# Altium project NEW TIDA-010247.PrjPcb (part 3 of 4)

## Sheet High side FETs.SchDoc
size A2; SheetNumber: 5; SheetTotal: 10
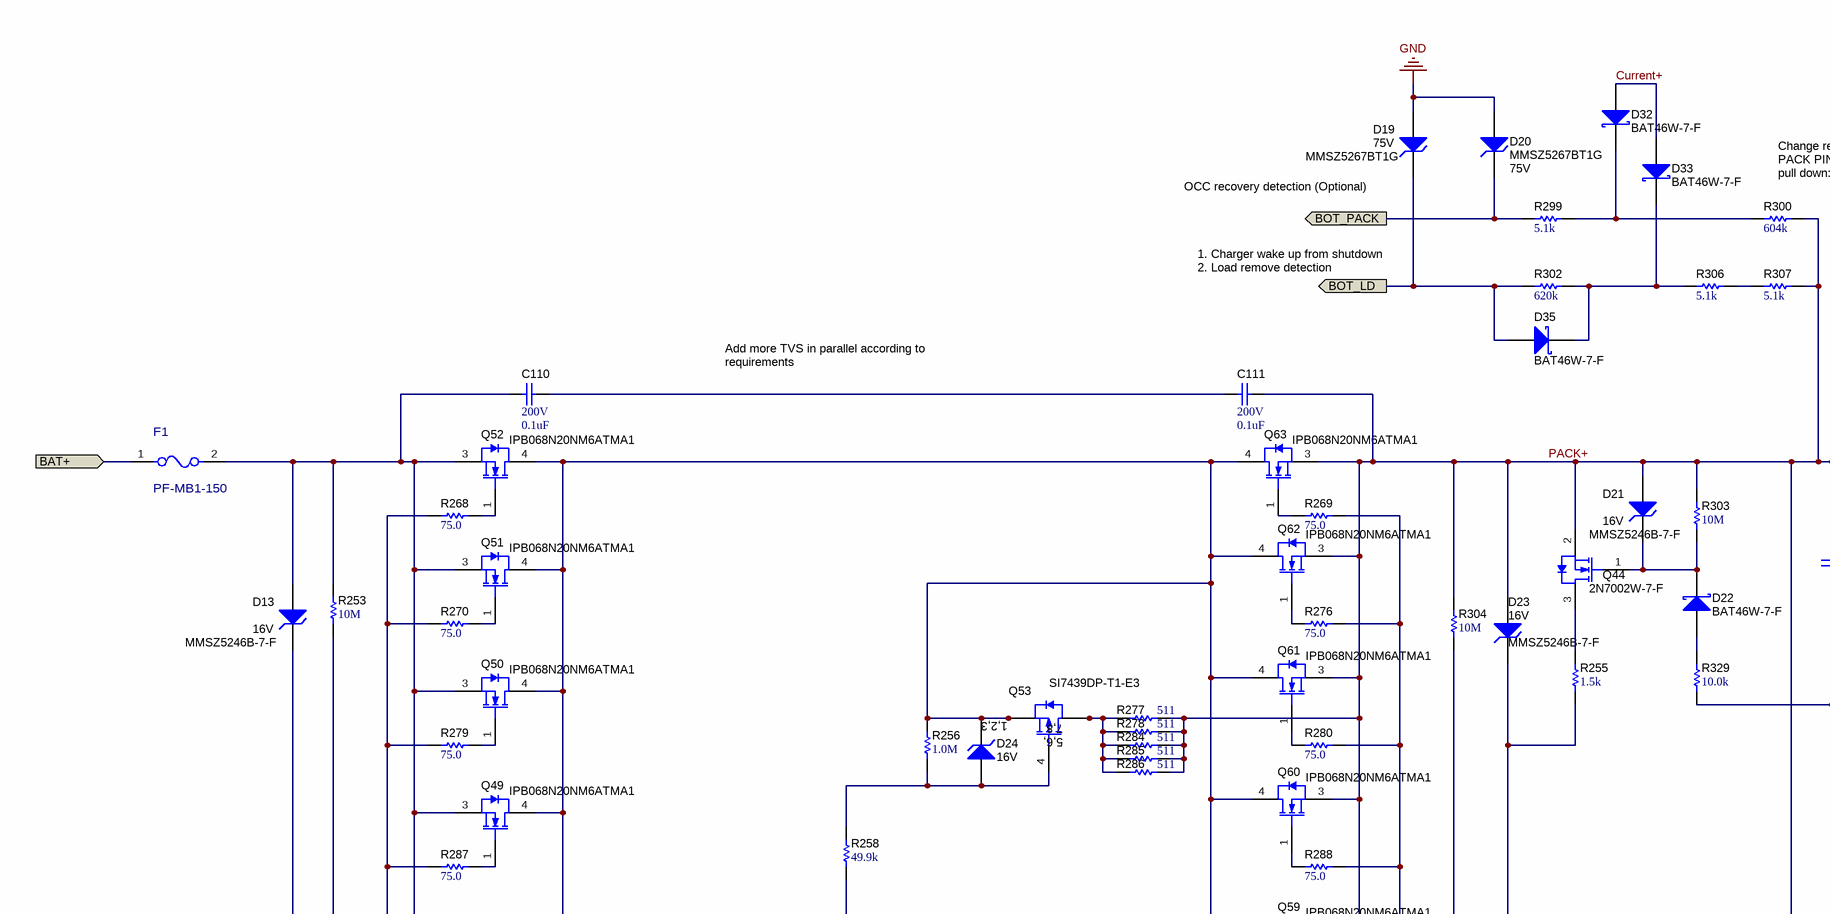
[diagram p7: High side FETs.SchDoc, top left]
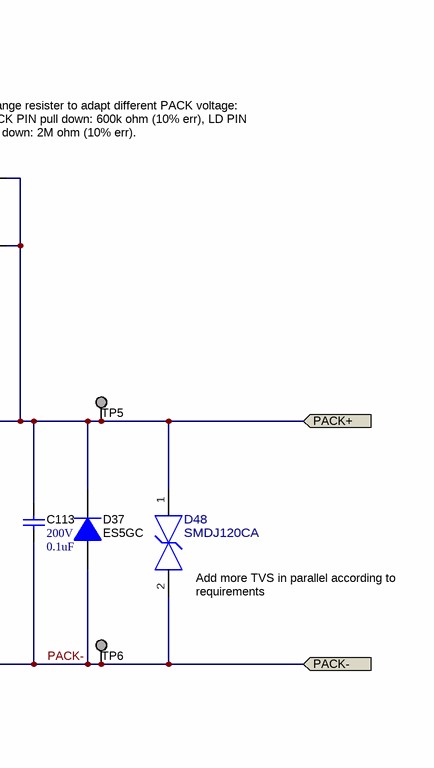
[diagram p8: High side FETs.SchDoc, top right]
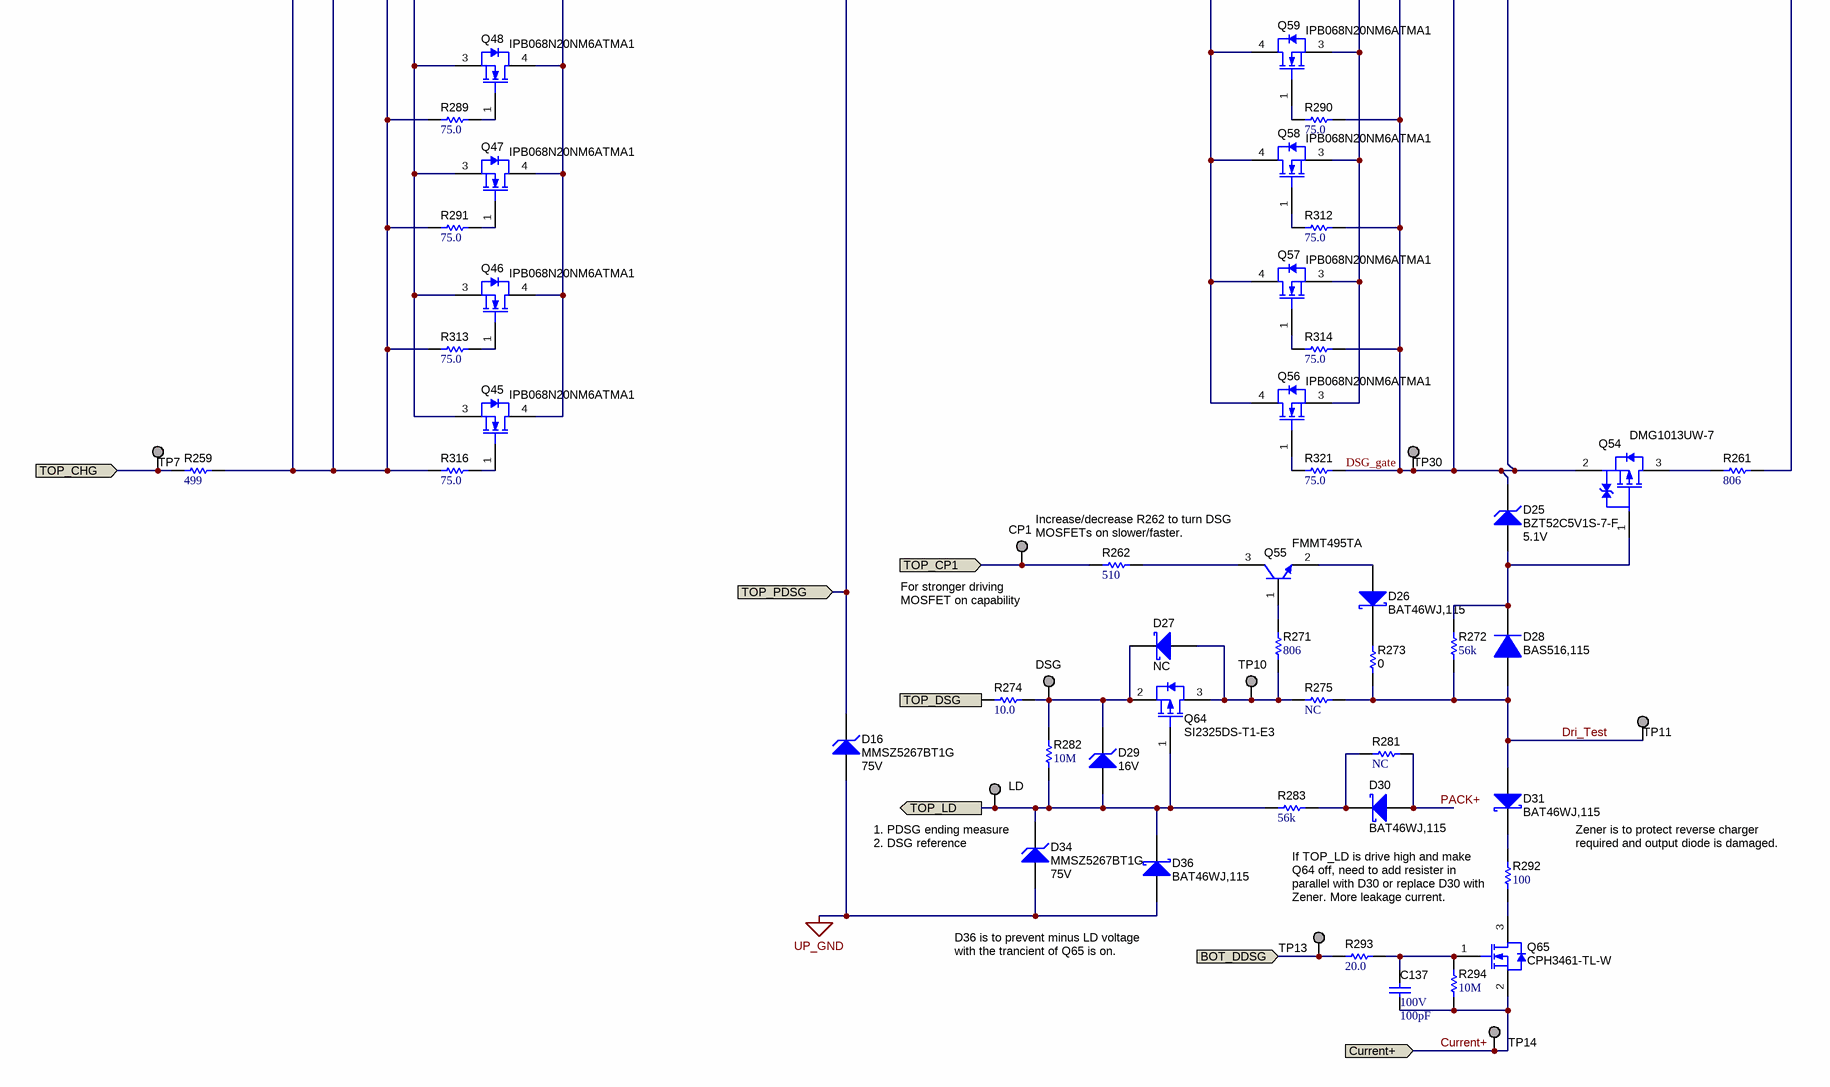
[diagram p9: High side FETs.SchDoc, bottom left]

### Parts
C110  VDC_V: 200V  ValueDisplayed: 0.1uF  [1206]  (hidden comment: C1206C104K2RACTU)
C111  VDC_V: 200V  ValueDisplayed: 0.1uF  [1206]  (hidden comment: C1206C104K2RACTU)
C113  VDC_V: 200V  ValueDisplayed: 0.1uF  [1206]  (hidden comment: C1206C104K2RACTU)
C137  VDC_V: 100V  ValueDisplayed: 100pF  [0603]  (hidden comment: GRM1885C2A101JA01D)  (no BOM)
CP1    [TP_SM_1MM]  (value not drawn)  (no BOM)
D13  MMSZ5246B-7-F  value 16V  [SOD-123]
D16  MMSZ5267BT1G  value 75V  [SOD-123]
D19  MMSZ5267BT1G  value 75V  [SOD-123]
D20  MMSZ5267BT1G  value 75V  [SOD-123]
D21  MMSZ5246B-7-F  value 16V  [SOD-123]
D22  BAT46W-7-F  [SOD-123]
D23  MMSZ5246B-7-F  value 16V  [SOD-123]
D24  value 16V  [SOD-123]  (hidden comment: MMSZ5246B-7-F)
D25  BZT52C5V1S-7-F  value 5.1V  [SOD-323]
D26  BAT46WJ,115  [SOD-323F]
D27  NC  [SOD-323F]  (no BOM)
D28  BAS516,115  [SOD-523]
D29  value 16V  [SOD-123]  (hidden comment: MMSZ5246B-7-F)
D30  BAT46WJ,115  [SOD-323F]
D31  BAT46WJ,115  [SOD-323F]
D32  BAT46W-7-F  [SOD-123]
D33  BAT46W-7-F  [SOD-123]
D34  MMSZ5267BT1G  value 75V  [SOD-123]
D35  BAT46W-7-F  [SOD-123]
D36  BAT46WJ,115  [SOD-323F]
D37  ES5GC  [SMC]
D48  SMDJ120CA  [FP-SMDJ54CA_DO-214AB-MFG]
DSG    [TP_SM_1MM]  (value not drawn)  (no BOM)
F1  PF-MB1-150  [FP-PF-MB1-150_BT_FUSE_56MM0_17MM4-MFG]
LD    [TP_SM_1MM]  (value not drawn)  (no BOM)
Q44  2N7002W-7-F  [SOT-323]
Q45  IPB068N20NM6ATMA1  [DDPAK]
Q46  IPB068N20NM6ATMA1  [DDPAK]
Q47  IPB068N20NM6ATMA1  [DDPAK]
Q48  IPB068N20NM6ATMA1  [DDPAK]
Q49  IPB068N20NM6ATMA1  [DDPAK]
Q50  IPB068N20NM6ATMA1  [DDPAK]
Q51  IPB068N20NM6ATMA1  [DDPAK]
Q52  IPB068N20NM6ATMA1  [DDPAK]
Q53  SI7439DP-T1-E3  [PowerPAK_SO-8]
Q54  DMG1013UW-7  [SOT-323]
Q55  FMMT495TA  [SOT-23]
Q56  IPB068N20NM6ATMA1  [DDPAK]
Q57  IPB068N20NM6ATMA1  [DDPAK]
Q58  IPB068N20NM6ATMA1  [DDPAK]
Q59  IPB068N20NM6ATMA1  [DDPAK]
Q60  IPB068N20NM6ATMA1  [DDPAK]
Q61  IPB068N20NM6ATMA1  [DDPAK]
Q62  IPB068N20NM6ATMA1  [DDPAK]
Q63  IPB068N20NM6ATMA1  [DDPAK]
Q64  SI2325DS-T1-E3  [SOT-23]
Q65  CPH3461-TL-W  [SOT-23]
R253  ValueDisplayed: 10M  [0603]  (hidden comment: CRCW060310M0JNEA)
R255  ValueDisplayed: 1.5k  [0805_HV]  (hidden comment: CRCW08051K50JNEA)
R256  ValueDisplayed: 1.0M  [0603]  (hidden comment: CRCW06031M00JNEA)
R258  ValueDisplayed: 49.9k  [0603]  (hidden comment: RT0603BRD0749K9L)
R259  ValueDisplayed: 499  [0603]  (hidden comment: RC0603FR-07499RL)
R261  ValueDisplayed: 806  [0603]  (hidden comment: CRCW0603806RFKEA)
R262  ValueDisplayed: 510  [0603]  (hidden comment: RC0603FR-07510RL)
R268  ValueDisplayed: 75.0  [0603]  (hidden comment: CRCW060375R0FKEA)
R269  ValueDisplayed: 75.0  [0603]  (hidden comment: CRCW060375R0FKEA)
R270  ValueDisplayed: 75.0  [0603]  (hidden comment: CRCW060375R0FKEA)
R271  ValueDisplayed: 806  [0603]  (hidden comment: CRCW0603806RFKEA)
R272  ValueDisplayed: 56k  [0805_HV]  (hidden comment: CRCW080556K0JNEA)
R273  ValueDisplayed: 0  [0603]  (hidden comment: CRCW04020000Z0ED)
R274  ValueDisplayed: 10.0  [0805_HV]  (hidden comment: CRCW080510R0FKEA)
R275  ValueDisplayed: NC  [0603]  (hidden comment: CRCW0603806RFKEA)  (no BOM)
R276  ValueDisplayed: 75.0  [0603]  (hidden comment: CRCW060375R0FKEA)
R277  ValueDisplayed: 511  [1206]  (hidden comment: CRCW1206511RFKEA)
R278  ValueDisplayed: 511  [1206]  (hidden comment: CRCW1206511RFKEA)
R279  ValueDisplayed: 75.0  [0603]  (hidden comment: CRCW060375R0FKEA)
R280  ValueDisplayed: 75.0  [0603]  (hidden comment: CRCW060375R0FKEA)
R281  ValueDisplayed: NC  [0603]  (hidden comment: CRCW060310M0JNEA)  (no BOM)
R282  ValueDisplayed: 10M  [0603]  (hidden comment: CRCW060310M0JNEA)
R283  ValueDisplayed: 56k  [0805_HV]  (hidden comment: CRCW080556K0JNEA)
R284  ValueDisplayed: 511  [1206]  (hidden comment: CRCW1206511RFKEA)
R285  ValueDisplayed: 511  [1206]  (hidden comment: CRCW1206511RFKEA)
R286  ValueDisplayed: 511  [1206]  (hidden comment: CRCW1206511RFKEA)
R287  ValueDisplayed: 75.0  [0603]  (hidden comment: CRCW060375R0FKEA)
R288  ValueDisplayed: 75.0  [0603]  (hidden comment: CRCW060375R0FKEA)
R289  ValueDisplayed: 75.0  [0603]  (hidden comment: CRCW060375R0FKEA)
R290  ValueDisplayed: 75.0  [0603]  (hidden comment: CRCW060375R0FKEA)
R291  ValueDisplayed: 75.0  [0603]  (hidden comment: CRCW060375R0FKEA)
R292  ValueDisplayed: 100  [0603]  (hidden comment: CRCW0603100RFKEA)
R293  ValueDisplayed: 20.0  [0603]  (hidden comment: RC0603FR-0720RL)
R294  ValueDisplayed: 10M  [0603]  (hidden comment: CRCW060310M0JNEA)
R299  ValueDisplayed: 5.1k  [0603]  (hidden comment: CRCW06035K10JNEA)
R300  ValueDisplayed: 604k  [0603]  (hidden comment: RC0603FR-07604KL)
R302  ValueDisplayed: 620k  [0603]  (hidden comment: RC0603FR-07620KL)
R303  ValueDisplayed: 10M  [0603]  (hidden comment: CRCW060310M0JNEA)
R304  ValueDisplayed: 10M  [0603]  (hidden comment: CRCW060310M0JNEA)
R306  ValueDisplayed: 5.1k  [0603]  (hidden comment: CRCW06035K10JNEA)
R307  ValueDisplayed: 5.1k  [0603]  (hidden comment: CRCW06035K10JNEA)
R312  ValueDisplayed: 75.0  [0603]  (hidden comment: CRCW060375R0FKEA)
R313  ValueDisplayed: 75.0  [0603]  (hidden comment: CRCW060375R0FKEA)
R314  ValueDisplayed: 75.0  [0603]  (hidden comment: CRCW060375R0FKEA)
R316  ValueDisplayed: 75.0  [0603]  (hidden comment: CRCW060375R0FKEA)
R321  ValueDisplayed: 75.0  [0603]  (hidden comment: CRCW060375R0FKEA)
R329  ValueDisplayed: 10.0k  [0603]  (hidden comment: CRCW060310K0FKEA)
TP5    [TP_SM_1MM]  (value not drawn)  (no BOM)
TP6    [TP_SM_1MM]  (value not drawn)  (no BOM)
TP7    [TP_SM_1MM]  (value not drawn)  (no BOM)
TP10    [TP_SM_1MM]  (value not drawn)  (no BOM)
TP11    [TP_SM_1MM]  (value not drawn)  (no BOM)
TP13    [TP_SM_1MM]  (value not drawn)  (no BOM)
TP14    [TP_SM_1MM]  (value not drawn)  (no BOM)
TP30  DSG_GATE  [TP_SM_1MM]  (value not drawn)  (no BOM)

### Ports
BAT+ (in), BOT_DDSG (in), BOT_LD (out), BOT_PACK (out), Current+ (in), PACK+ (in), PACK- (in), TOP_CHG (in), TOP_CP1 (in), TOP_DSG (in), TOP_LD (out), TOP_PDSG (in)

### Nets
GND: D19.2(A) D20.2(A)
UP_GND: D16.2(A) D34.2(A) D36.2(A)
BAT+: F1.1 ; port BAT+
BOT_DDSG: R293.1 TP13.1 ; port BOT_DDSG
BOT_LD: D19.1(K) D35.2(A) R302.1 ; port BOT_LD
BOT_PACK: D20.1(K) R299.1 ; port BOT_PACK
Current+: C137.2 D32.2(A) D33.2(A) Q65.2(S) R294.1 TP14.1 ; port Current+
Dri_Test: D28.2(A) D31.2(A) R272.1 R273.1 R275.1 TP11.1
DSG_gate: D23.1(K) D25.1(K) Q54.2(S) R255.1 R269.2 R276.2 R280.2 R288.2 R290.2 R304.1 R312.2 R314.2 R321.2 TP30.1
PACK+: C111.1 C113.1 D21.2(A) D23.2(A) D30.2(A) D37.1(K) D48.1 Q44.2(S) Q56.3(S) Q57.3(S) Q58.3(S) Q59.3(S) Q60.3(S) Q61.3(S) Q62.3(S) Q63.3(S) R261.1 R277.2 R278.2 R281.1 R284.2 R285.2 R286.2 R300.2 R303.2 R304.2 R307.2 TP5.1 ; port PACK+
PACK-: C113.2 D37.2(A) D48.2 R329.1 TP6.1 ; port PACK-
TOP_CHG: R259.1 TP7.1 ; port TOP_CHG
TOP_CP1: CP1.1 R262.1 ; port TOP_CP1
TOP_DSG: R274.1 ; port TOP_DSG
TOP_LD: D29.2(A) D34.1(K) D36.1(K) LD.1 Q64.1(G) R282.1 R283.2 ; port TOP_LD
TOP_PDSG: D16.1(K) R258.1 ; port TOP_PDSG
NetC110_1: C110.1 C111.2
NetC110_2: C110.2 D13.2(A) F1.2 Q45.3(S) Q46.3(S) Q47.3(S) Q48.3(S) Q49.3(S) Q50.3(S) Q51.3(S) Q52.3(S) R253.2
NetC137_1: C137.1 Q65.1(G) R293.2 R294.2
NetD13_1: D13.1(K) R253.1 R259.2 R268.1 R270.1 R279.1 R287.1 R289.1 R291.1 R313.1 R316.1
NetD21_1: D21.1(K) D22.1(K) Q44.1(G) R303.1
NetD22_2: D22.2(A) R329.2
NetD24_1: D24.1(K) Q45.4(D) Q46.4(D) Q47.4(D) Q48.4(D) Q49.4(D) Q50.4(D) Q51.4(D) Q52.4(D) Q53.1(S) Q53.2(S) Q53.3(S) Q56.4(D) Q57.4(D) Q58.4(D) Q59.4(D) Q60.4(D) Q61.4(D) Q62.4(D) Q63.4(D) R256.2
NetD24_2: D24.2(A) Q53.4(G) R256.1 R258.2
NetD25_2: D25.2(A) D28.1(K) Q54.1(G) R272.2
NetD26_1: D26.1(K) R273.2
NetD26_2: D26.2(A) Q55.2(E)
NetD27_1: D27.1(K) D29.1(K) DSG.1 Q64.2(S) R274.2 R282.2
NetD27_2: D27.2(A) Q64.3(D) R271.1 R275.2 TP10.1
NetD30_1: D30.1(K) R281.2 R283.1
NetD31_1: D31.1(K) R292.2
NetD32_1: D32.1(K) R299.2 R300.1
NetD33_1: D33.1(K) D35.1(K) R302.2 R306.1
NetQ44_3: Q44.3(D) R255.2
NetQ45_1: Q45.1(G) R316.2
NetQ46_1: Q46.1(G) R313.2
NetQ47_1: Q47.1(G) R291.2
NetQ48_1: Q48.1(G) R289.2
NetQ49_1: Q49.1(G) R287.2
NetQ50_1: Q50.1(G) R279.2
NetQ51_1: Q51.1(G) R270.2
NetQ52_1: Q52.1(G) R268.2
NetQ53_5: Q53.5(D) Q53.6(D) Q53.7(D) Q53.8(D) Q53.9(D) R277.1 R278.1 R284.1 R285.1 R286.1
NetQ54_3: Q54.3(D) R261.2
NetQ55_1: Q55.1(B) R271.2
NetQ55_3: Q55.3(C) R262.2
NetQ56_1: Q56.1(G) R321.1
NetQ57_1: Q57.1(G) R314.1
NetQ58_1: Q58.1(G) R312.1
NetQ59_1: Q59.1(G) R290.1
NetQ60_1: Q60.1(G) R288.1
NetQ61_1: Q61.1(G) R280.1
NetQ62_1: Q62.1(G) R276.1
NetQ63_1: Q63.1(G) R269.1
NetQ65_3: Q65.3(D) R292.1
NetR306_2: R306.2 R307.1

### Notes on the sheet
- (near D19) OCC recovery detection (Optional)
- (near R300) Change resister to adapt different PACK voltage: PACK PIN pull down: 600k ohm (10% err), LD PIN pull down: 2M ohm (10% err).
- 1. Charger wake up from shutdown
  2. Load remove detection
- Add more TVS in parallel according to requirements
- (near D48) Add more TVS in parallel according to requirements
- Increase/decrease R262 to turn DSG MOSFETs on slower/faster.
- (near CP1) For stronger driving MOSFET on capability
- (near D34) 1. PDSG ending measure
  2. DSG reference
- Zener is to protect reverse charger required and output diode is damaged.
- (near R292) If TOP_LD is drive high and make Q64 off, need to add resister in parallel with D30 or replace D30 with Zener. More leakage current.
- D36 is to prevent minus LD voltage with the trancient of Q65 is on.

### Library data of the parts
C110 C111 C113 = CMP-0008585-2: CAP, CERM, 0.1 uF, 200 V, +/- 10%, X7R, 1206; Manufacturer: Kemet; TaMin_C: -55°C; Polarized: N; SizeAreaWB_mm2: 10.92; Value1: Unknown; U/M: EA; Value: 0.1uF; TaMax_C: 125°C; SizeZ_mm: 1.35; SizeX_mm: 3.2; SizeY_mm: 1.6; SizeArea_mm2: 5.12; Cap_F: 100nF; AEC Category: Q200
C137 = CMP-0007237-4: CAP, CERM, 100 pF, 100 V, +/- 5%, C0G/NP0, 0603; Manufacturer: MuRata; TaMin_C: -55°C; Polarized: N; SizeAreaWB_mm2: 4.68; Value1: Unknown; U/M: EA; Value: 100pF; TaMax_C: 125°C; SizeZ_mm: 1; SizeX_mm: 1.6; SizeY_mm: 0.8; SizeArea_mm2: 1.28; AEC Category: Q200
CP1 DSG LD TP5-TP7 TP10 TP11 TP13 TP14 TP30 = CMP-0003825-1: 1mm Test Point, SMT; Manufacturer: Any
D13 D21 D23 D24 D29 = CMP-0005754-4: Diode, Zener, 16 V, 500 mW, SOD-123; Manufacturer: Diodes Inc.; Power_W: 500mW; SizeY_mm: 1.7; Value1: 0.5W; SizeX_mm: 3.85; RJA_CperW: 350; SizeAreaWB_mm2: 13.095; SizeArea_mm2: 6.545; AEC Category: Q101; SizeZ_mm: 1.35
D16 D19 D20 D34 = CMP-0005738-1: Diode, Zener, 75V, 500 mW, AEC-Q101, SOD-123; Manufacturer: ON Semiconductor; PartNumber: MMSZ5263BT1G; Power_W: 500mW; SizeAreaWB_mm2: 13.095; Vz_V: 56V; Value1: 0.5W; RJA_CperW: 340; U/M: EA; SizeZ_mm: 1.35; SizeX_mm: 3.85; SizeY_mm: 1.7; SizeArea_mm2: 6.545; AEC Qualified: Y; AEC Category: Q101
D22 D32 D33 D35 = CMP-0028450-2: Diode, Schottky, 100 V, 0.15 A, SOD-123; Manufacturer: Diodes Inc.; Value: 100V; Io_A: 150mA; SizeArea_mm2: 6.545; SizeX_mm: 3.85; Value2: 0.6V; Value1: 0.15A; AEC Category: Q101; SizeZ_mm: 1.35; SizeY_mm: 1.7; Green_Lifecycle: Active; Green_REACh: Passed; SizeAreaWB_mm2: 13.095; Vf_V: 600mV
D25 = CMP-0005865-2: Diode, Zener, 5.1 V, 200 mW, SOD-323; Manufacturer: Diodes Inc.; SizeY_mm: 1.35; SizeZ_mm: 1; AEC Category: Q101; Power_W: 200mW; SizeX_mm: 2.7; SizeAreaWB_mm2: 8.695; RJA_CperW: 625; SizeArea_mm2: 3.645; Value1: 0.2W
D26 D30 D31 D36 = CMP-0076946-1: Diode, Schottky, 100 V, 0.25 A, SOD-323F; Manufacturer: Nexperia; SizeAreaWB_mm2: 7.875; Vr_V: 100V; SizeArea_mm2: 3.125; TJmax_C: 150°C; AEC Category: Q101; Value: 100V; SizeZ_mm: 0.8; Green_REACh: Incomplete; Io_A: 250mA; Vf_V: 850mV; SizeY_mm: 1.25; Value2: 0.85V; Green_Lifecycle: Not Set; U/M: EA; Value1: 0.25A; SizeX_mm: 2.5
D27 = CMP-0076946-1: Diode, Schottky, 100 V, 0.25 A, SOD-323F; PartNumber: BAT46WJ,115; Manufacturer: Nexperia; SizeAreaWB_mm2: 7.875; Vr_V: 100V; SizeArea_mm2: 3.125; TJmax_C: 150°C; AEC Category: Q101; Value: 100V; SizeZ_mm: 0.8; Green_REACh: Incomplete; Io_A: 250mA; Vf_V: 850mV; SizeY_mm: 1.25; Value2: 0.85V; Green_Lifecycle: Not Set; U/M: EA; Value1: 0.25A; SizeX_mm: 2.5
D28 = CMP-0076979-1: Diode, Switching, 100 V, 0.25 A, SOD-523; Manufacturer: Nexperia; SizeAreaWB_mm2: 5.13; Vr_V: 100V; SizeArea_mm2: 1.53; TJmax_C: 150°C; AEC Category: Q101; Value: 100V; SizeZ_mm: 0.65; Green_REACh: Incomplete; Io_A: 250mA; Vf_V: 1.25V; SizeY_mm: 0.9; Green_Lifecycle: Not Set; U/M: EA; Value1: 0.25A; SizeX_mm: 1.7
D37 = CMP-0029041-2: Diode, Ultrafast, 200 V, 3 A, SMC; Manufacturer: MDD; Io_A: 5A; Vf_V: 900mV; SizeAreaWB_mm2: 83.2686; TJmax_C: 150°C; SizeArea_mm2: 50.5686; AEC Category: Q101; Vr_V: 400V; Value2: 0.9V; Green_Lifecycle: Not Set; SizeZ_mm: 2.6; SizeX_mm: 8.13; Green_REACh: Incomplete; Value: 400V; SizeY_mm: 6.22
D48 = CMP-0001373-1: Diode, TVS, Bi, 120 V，3000 W,SMD (non-polarized); Manufacturer: Littelfuse Inc; AEC Qualified: No; SizeZ_mm: 2.62mm; VRWM: 54V; Ipp: 34.4A; Ppk: 3kW; Breakdown Voltage: 60V; Clamping Voltage: 87.1V; Direction: Bidirectional; Number Of Channels: 1; TJmax_C: +150°C
F1 = CMP-0122193-1: Fuse Power 150A 240V Bolt Flat 56 X 17.4 X 19.1mm; Manufacturer: Bourns; Interrupt_AC: 160kA; Interrupt_DC: 50kA; MeltingTyp: 15100A2Sec; SizeZ_mm: 19.3mm; Fuse Speed: Medium; AEC Qualified: No; Fuse Interrupt Dc Current: 50000A; Res_ohm: 0.00049Ω
Q44 = CMP-0000776-1: MOSFET, N-CH, 60 V, 0.115 A, SOT-323; Alternate Manufacturer: None; Manufacturer: Diodes Inc.; SizeZ_mm: 1.1; ChType: N; Value1: 7; VdsMax_V: 60V; SizeX_mm: 2.2; Vgs_V: 20V; Value: 60V; Rdson45_ohm: 7.5; SizeArea_mm2: 4.84; AEC Category: Q101; IdsMax_A: 115mA; SizeAreaWB_mm2: 10.24; U/M: EA
Q45-Q52 Q56-Q63 = CMP-0001086-1: MOSFET, N-CH, 200 V, 134A, DDPAK; Alternate Manufacturer: None; Manufacturer: Infineon Technologies; SizeZ_mm: 4.445; ChType: N; Value2: 70 nC; VdsMax_V: 200V; SizeX_mm: 15.245; SizeY_mm: 10.16; Vgs_V: 3.7V; Value: 200V; SizeArea_mm2: 154.8892; AEC Category: Q101; IdsMax_A: 62A; SizeAreaWB_mm2: 209.6992; U/M: EA; QgTyp_nC: 70
Q53 = CMP-0000116-2: MOSFET, P-CH, -150 V, -3 A, PowerPAK SO-8; Alternate Manufacturer: None; Manufacturer: Vishay-Siliconix; SizeZ_mm: 1.12; ChType: P; Value2: 88 nC; VdsMax_V: -150V; SizeX_mm: 5.99; SizeY_mm: 4.9; Vgs_V: -20V; Value: -150V; SizeArea_mm2: 29.351; AEC Category: Q101; IdsMax_A: -3A; SizeAreaWB_mm2: 55.131; U/M: EA; QgTyp_nC: 88
Q54 = CMP-0000035-3: MOSFET, P-CH, -20 V, -0.82 A, SOT-323; Manufacturer: Diodes Inc.; Alternate Manufacturer: None; AEC Category: Q101; Value: -20V; Rdson45_ohm: 0.75; SizeX_mm: 2.2; Vgs_V: -6V; SizeZ_mm: 1.1; SizeAreaWB_mm2: 10.24; ChType: P; ChMode: Enhancement; QgTyp_nC: 0.622; SizeArea_mm2: 4.84; Value2: 0.622 nC; Value1: 0.7; IdsMax_A: -820mA
Q55 = CMP-0074710-1: Transistor, NPN, 150 V, 1 A, AEC-Q101, SOT-23; Manufacturer: Diodes Inc.; TaMin_C: -55°C; HfeMax: 300.0; SizeAreaWB_mm2: 14.0; Value1: 1 A; Vceo_V: 150V; U/M: EA; Value: 150 V; TaMax_C: 150°C; IcRated_A: 1A; SizeZ_mm: 1.1; SizeX_mm: 2.5; SizeY_mm: 3.0; SizeArea_mm2: 7.5; CompType: BJT; PNP: 0.0; AEC Qualified: Y; NPN: 1.0; Vcesat1_V: 300mV; AEC Category: Q101
Q64 = CMP-0000093-2: MOSFET, P-CH, -150 V, -0.53 A, SOT-23; Alternate Manufacturer: None; Manufacturer: Vishay-Siliconix; SizeZ_mm: 1.1; ChType: P; Value2: 7.7 nC; VdsMax_V: -150V; SizeX_mm: 2.5; SizeY_mm: 3; Vgs_V: -20V; AEC Qualified: N; Value: -150V; SizeArea_mm2: 7.5; AEC Category: Q101; IdsMax_A: -530mA; SizeAreaWB_mm2: 14; U/M: EA; QgTyp_nC: 7.7
Q65 = CMP-0000947-2: MOSFET, N-CH, 100 V, 0.17 A, SOT-23; Alternate Manufacturer: None; Manufacturer: Fairchild Semiconductor; SizeZ_mm: 1.1; ChType: N; Value2: 1.8 nC; Value1: 1; VdsMax_V: 100V; SizeX_mm: 2.5; SizeY_mm: 3; Vgs_V: 20V; Value: 100V; Rdson45_ohm: 10; SizeArea_mm2: 7.5; AEC Category: Q101; IdsMax_A: 170mA; SizeAreaWB_mm2: 14; U/M: EA; QgTyp_nC: 1.8
R253 R282 R294 R303 R304 = CMP-0025702-4: RES, 10 M, 5%, 0.1 W, AEC-Q200 Grade 0, 0603; Manufacturer: Vishay-Dale; Power_W: 100mW; TempCo: 200 ppm/C; Value_Code: 10M0; Value: 10Meg; EIA_Code: E24; SizeX_mm: 1.6; SizeY_mm: 0.8; SizeZ_mm: 1; Value2: 0.1W; SizeArea_mm2: 1.28; AEC Qualified: Y; VDC_V: 75V; AEC Category: Q200; AEC Grade: 0
R255 = CMP-0020477-3: RES, 1.5 k, 5%, 0.125 W, AEC-Q200 Grade 0, 0805; Manufacturer: Vishay-Dale; Power_W: 125mW; TempCo: 200 ppm/C; Value_Code: 1k50; Value: 1.5k; EIA_Code: E24; SizeX_mm: 2; SizeY_mm: 1.25; SizeZ_mm: 1.45; Value2: 0.125W; SizeArea_mm2: 2.5; AEC Qualified: Y; VDC_V: 150V; AEC Category: Q200; AEC Grade: 0
R256 = CMP-0025736-3: RES, 1.0 M, 5%, 0.1 W, 0603; Manufacturer: Vishay-Dale; Power_W: 100mW; TempCo: 200 ppm/C; Value_Code: 1M00; U/M: EA; Value: 1.0Meg; EIA_Code: E24; Res_ohm: 1M; SizeX_mm: 1.6; SizeY_mm: 0.8; SizeZ_mm: 1; Value2: 0.1W; SizeArea_mm2: 1.28; VDC_V: 75V; AEC Category: Q200
R258 = CMP-0024283-1: RES, 49.9 k, 0.1%, 0.1 W, 0603; Manufacturer: Yageo America; Power_W: 100mW; TempCo: 25 ppm/C; Value_Code: 49k9; U/M: EA; Value: 49.9k; EIA_Code: E192; SizeX_mm: 1.6; SizeY_mm: 0.8; SizeZ_mm: 1; Value2: 0.1W; SizeArea_mm2: 1.28; VDC_V: 75V; AEC Category: Q200
R259 = CMP-0023141-5: RES, 499, 1%, 0.1 W, 0603; Manufacturer: Yageo; Power_W: 100mW; TempCo: 100 ppm/C; Value_Code: 499R; Value: 499; EIA_Code: E96; SizeX_mm: 1.6; SizeY_mm: 0.8; SizeZ_mm: 1; Value2: 0.1W; SizeArea_mm2: 1.28; AEC Qualified: N; VDC_V: 75V; AEC Category: Q200; SizeAreaWB_mm2: 4.68
R261 R271 R275 = CMP-0022615-1: RES, 806, 1%, 0.1 W, 0603; Manufacturer: Vishay-Dale; Power_W: 100mW; TempCo: 100 ppm/C; Value_Code: 806R; U/M: EA; Value: 806; EIA_Code: E96; SizeX_mm: 1.6; SizeY_mm: 0.8; SizeZ_mm: 1; Value2: 0.1W; SizeArea_mm2: 1.28; VDC_V: 75V; AEC Category: Q200
R262 = CMP-0023163-5: RES, 510, 1%, 0.1 W, 0603; Manufacturer: Yageo; Power_W: 100mW; TempCo: 100 ppm/C; Value_Code: 510R; Value: 510; SizeX_mm: 1.6; SizeY_mm: 0.8; SizeZ_mm: 1; Value2: 0.1W; SizeArea_mm2: 1.28; AEC Qualified: N; VDC_V: 75V; AEC Category: Q200; SizeAreaWB_mm2: 4.68
R268-R270 R276 R279 R280 R287-R291 R312-R314 R316 R321 = CMP-0022590-3: RES, 75.0, 1%, 0.1 W, 0603; Manufacturer: Vishay-Dale; Power_W: 100mW; TempCo: 100 ppm/C; Value_Code: 75R0; U/M: EA; Value: 75.0; EIA_Code: E96; Res_ohm: 75; SizeX_mm: 1.6; SizeY_mm: 0.8; SizeZ_mm: 1; Value2: 0.1W; SizeArea_mm2: 1.28; VDC_V: 75V; AEC Category: Q200
R272 R283 = CMP-0020570-1: RES, 56 k, 5%, 0.125 W, 0805; Manufacturer: Vishay-Dale; Power_W: 125mW; TempCo: 200 ppm/C; Value_Code: 56k0; U/M: EA; Value: 56k; EIA_Code: E24; SizeX_mm: 2; SizeY_mm: 1.25; SizeZ_mm: 1.45; Value2: 0.125W; SizeArea_mm2: 2.5; VDC_V: 150V; AEC Category: Q200
R273 = CRCW04020000Z0ED: RES, 0, 5%, 0.063 W, 0402; Manufacturer: Vishay-Dale; CompType: Resistor; Value: 0; Value_Code: 0000; Tolerance_%: 5; Power_W: 0.063; Value2: 0.063W; VDC_V: 50; TempCo: 200 ppm/C; SizeArea_mm2: 0.5; SizeX_mm: 1; SizeZ_mm: 0.6; EIA_Code: E24; U/M: EA; AEC Category: Q200; Green_Lifecycle: Active; Green_REACh: Passed
R274 = CMP-0020847-1: RES, 10.0, 1%, 0.125 W, 0805; Manufacturer: Vishay-Dale; Power_W: 125mW; TempCo: 100 ppm/C; Value_Code: 10R0; U/M: EA; Value: 10.0; EIA_Code: E96; Res_ohm: 10; SizeX_mm: 2; SizeY_mm: 1.25; SizeZ_mm: 1.45; Value2: 0.125W; SizeArea_mm2: 2.5; VDC_V: 150V; AEC Category: Q200
R277 R278 R284-R286 = CMP-0017051-2: RES, 511, 1%, 0.25 W, 1206; Manufacturer: Vishay-Dale; Power_W: 250mW; TempCo: 100 ppm/C; Value_Code: 511R; U/M: EA; Value: 511; EIA_Code: E96; SizeX_mm: 3.2; SizeY_mm: 1.6; SizeZ_mm: 1.35; Value2: 0.25W; SizeArea_mm2: 5.12; VDC_V: 200V; AEC Category: Q200
R281 = CMP-0025702-4: RES, 10 M, 5%, 0.1 W, AEC-Q200 Grade 0, 0603; Manufacturer: Vishay-Dale; Power_W: 100mW; TempCo: 200 ppm/C; Value_Code: 10M0; Value: 10Meg; EIA_Code: E24; Res_ohm: 10M; SizeX_mm: 1.6; SizeY_mm: 0.8; SizeZ_mm: 1; Value2: 0.1W; SizeArea_mm2: 1.28; AEC Qualified: Y; VDC_V: 75V; AEC Category: Q200; AEC Grade: 0
R292 = CMP-0021991-2: RES, 100, 1%, 0.1 W, 0603; Manufacturer: Vishay-Dale; Power_W: 100mW; TempCo: 100 ppm/C; Value_Code: 100R; U/M: EA; Value: 100; EIA_Code: E96; SizeX_mm: 1.6; SizeY_mm: 0.8; SizeZ_mm: 1; Value2: 0.1W; SizeArea_mm2: 1.28; VDC_V: 75V; AEC Category: Q200
R293 = CMP-0022908-4: RES, 20.0, 1%, 0.1 W, 0603; Manufacturer: Yageo; Power_W: 100mW; TempCo: 100 ppm/C; Value_Code: 20R0; Value: 20.0; EIA_Code: E96; Res_ohm: 20; SizeX_mm: 1.6; SizeY_mm: 0.8; SizeZ_mm: 1; Value2: 0.1W; SizeArea_mm2: 1.28; AEC Qualified: N; VDC_V: 75V; AEC Category: Q200; SizeAreaWB_mm2: 4.68
R299 R306 R307 = CMP-0025830-2: RES, 5.1 k, 5%, 0.1 W, 0603; Manufacturer: Vishay-Dale; Power_W: 100mW; TempCo: 200 ppm/C; Value_Code: 5k10; U/M: EA; Value: 5.1k; EIA_Code: E24; SizeX_mm: 1.6; SizeY_mm: 0.8; SizeZ_mm: 1; Value2: 0.1W; SizeArea_mm2: 1.28; VDC_V: 75V; AEC Category: Q200
R300 = CMP-0023210-4: RES, 604 k, 1%, 0.1 W, 0603; Manufacturer: Yageo; Power_W: 100mW; TempCo: 100 ppm/C; Value: 604k; EIA_Code: E96; SizeX_mm: 1.6; SizeY_mm: 0.8; SizeZ_mm: 1; Value2: 0.1W; SizeArea_mm2: 1.28; AEC Qualified: N; VDC_V: 75V; AEC Category: Q200; SizeAreaWB_mm2: 4.68
R302 = CMP-0023218-4: RES, 620 k, 1%, 0.1 W, 0603; Manufacturer: Yageo; Power_W: 100mW; TempCo: 100 ppm/C; Value: 620k; SizeX_mm: 1.6; SizeY_mm: 0.8; SizeZ_mm: 1; Value2: 0.1W; SizeArea_mm2: 1.28; AEC Qualified: N; VDC_V: 75V; AEC Category: Q200; SizeAreaWB_mm2: 4.68
R329 = CMP-0021998-4: RES, 10.0 k, 1%, 0.1 W, AEC-Q200 Grade 0, 0603; Manufacturer: Vishay-Dale; Power_W: 100mW; TempCo: 100 ppm/C; Value_Code: 10k0; Value: 10.0k; EIA_Code: E96; Res_ohm: 10k; SizeX_mm: 1.6; SizeY_mm: 0.8; SizeZ_mm: 1; Value2: 0.1W; SizeArea_mm2: 1.28; AEC Qualified: Y; VDC_V: 75V; AEC Category: Q200; AEC Grade: 0

## Sheet AUX Power Supply.SchDoc
size A3; SheetNumber: 7; SheetTotal: 10
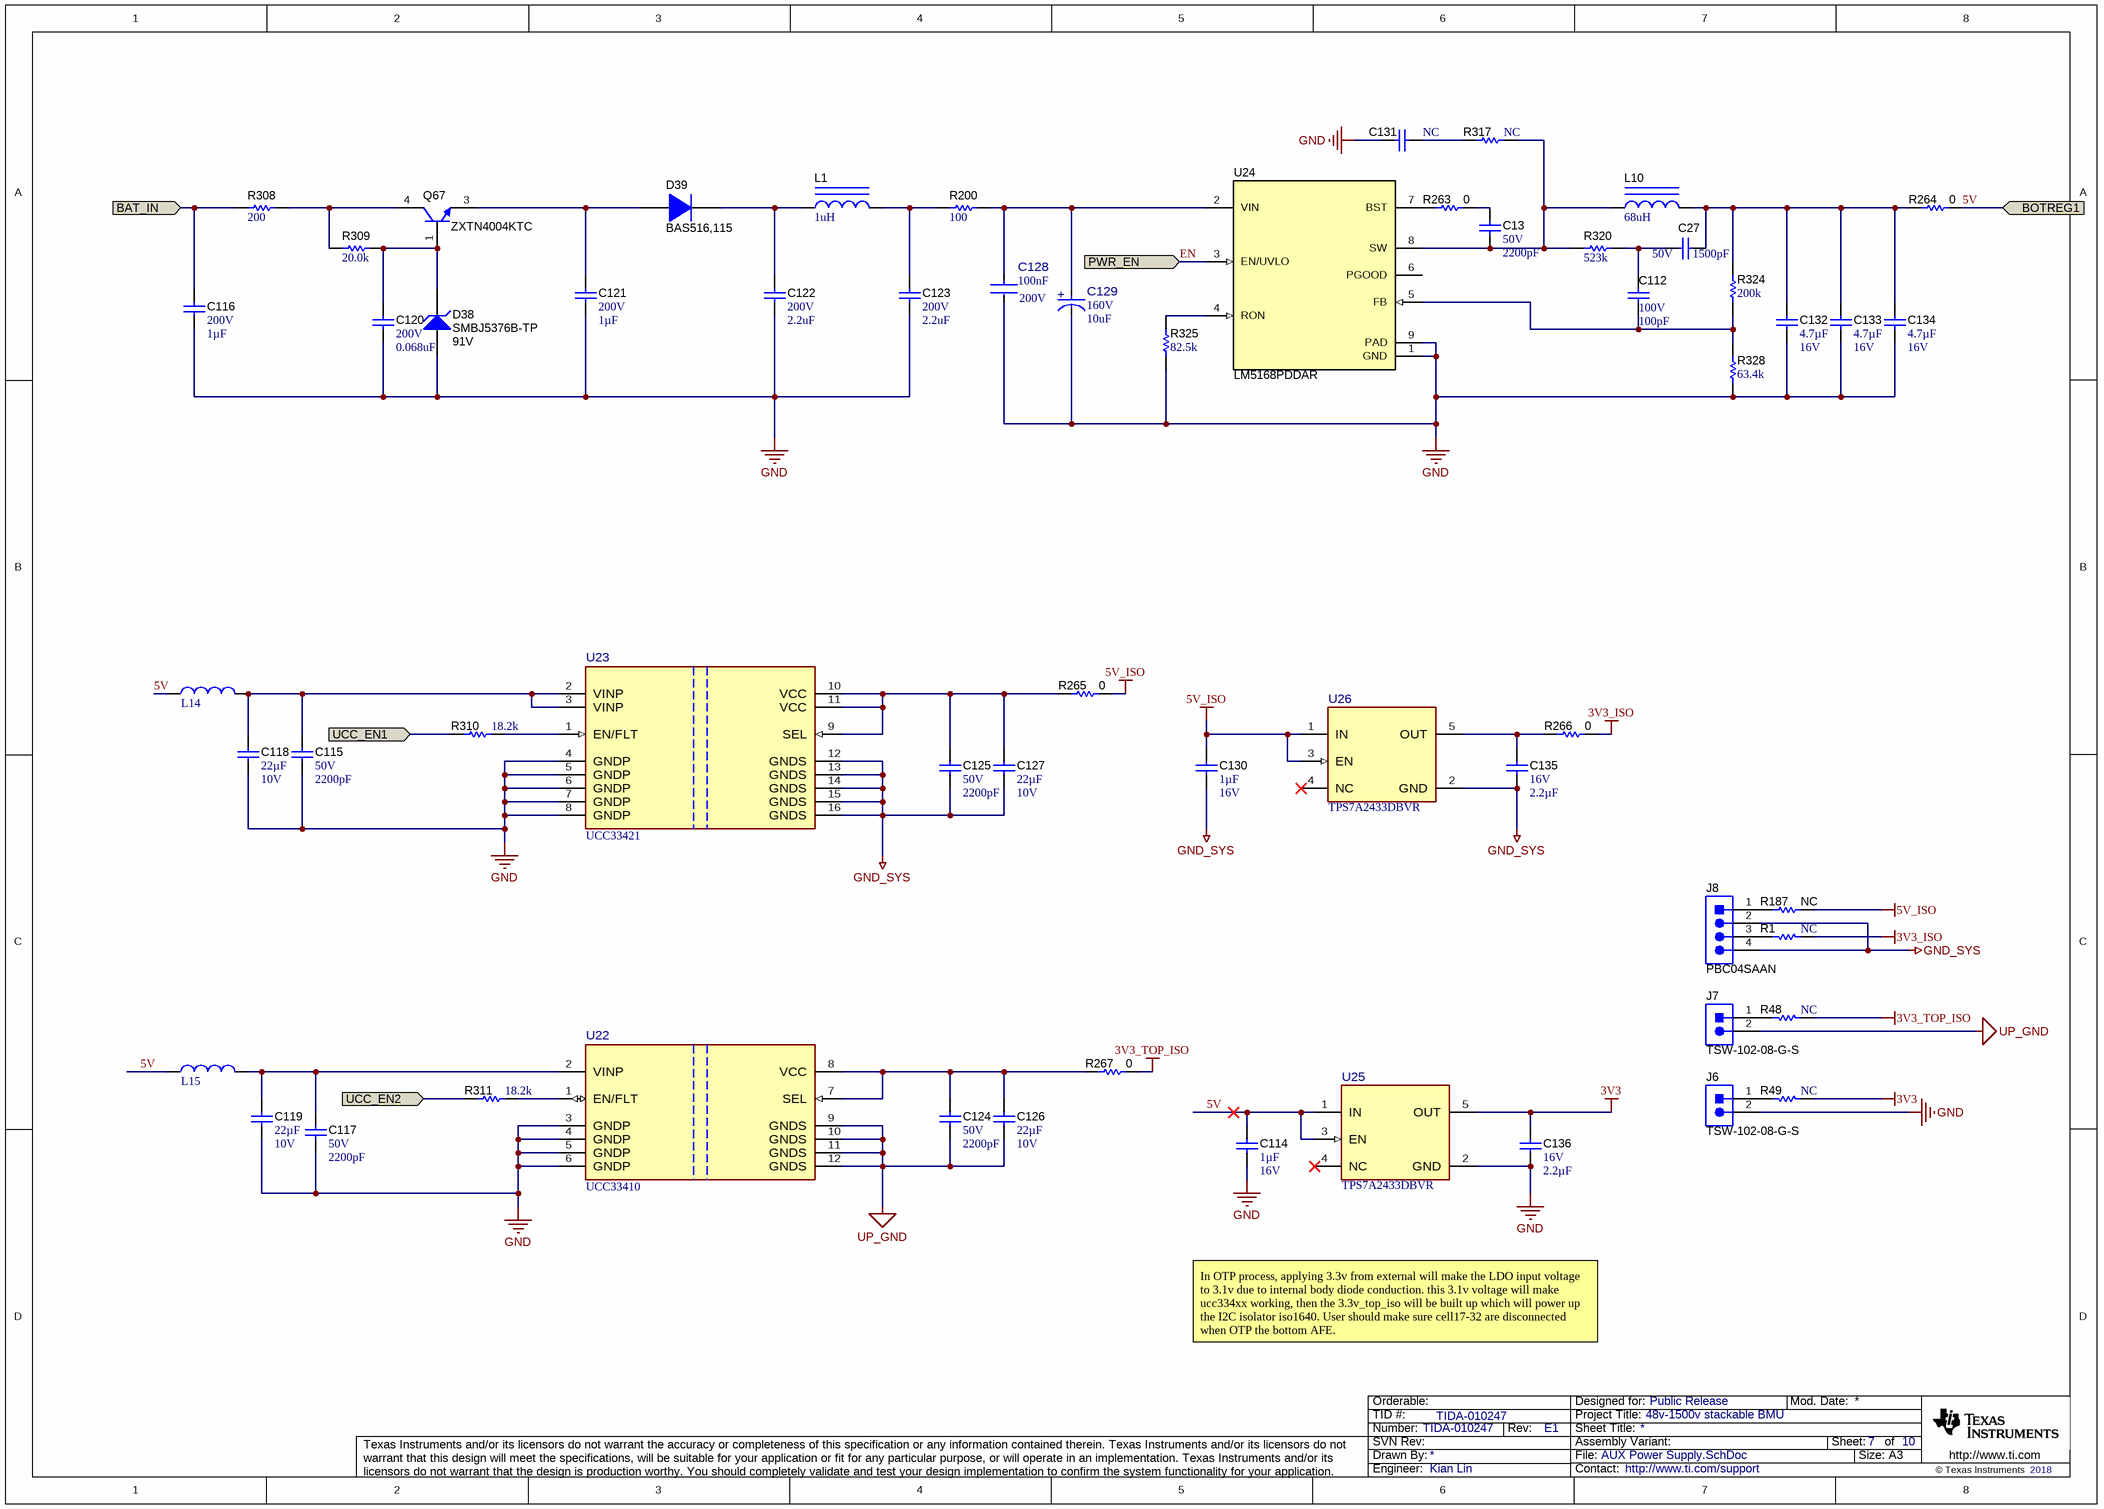
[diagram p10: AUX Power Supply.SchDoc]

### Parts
C13  VDC_V: 50V  ValueDisplayed: 2200pF  [0402]  (hidden comment: GRM155R71H222KA01D)
C27  VDC_V: 50V  ValueDisplayed: 1500pF  [0402]  (hidden comment: GRM155R71H152KA01D)
C112  VDC_V: 100V  ValueDisplayed: 100pF  [0603]  (hidden comment: GRM1885C2A101JA01D)
C114  Cap_F: 1µF  VDC_V: 16V  [0603]  (hidden comment: GCM188R71C105KA64D)
C115  VDC_V: 50V  ValueDisplayed: 2200pF  [0402]  (hidden comment: GCM155R71H222KA37D)
C116  VDC_V: 200V  ValueDisplayed: 1µF  [1812_280]  (hidden comment: 18122C105KAT2A)
C117  VDC_V: 50V  ValueDisplayed: 2200pF  [0402]  (hidden comment: GCM155R71H222KA37D)
C118  Cap_F: 22µF  VDC_V: 10V  [0805_HV]  (hidden comment: GRM21BZ71A226ME15L)
C119  Cap_F: 22µF  VDC_V: 10V  [0805_HV]  (hidden comment: GRM21BZ71A226ME15L)
C120  VDC_V: 200V  ValueDisplayed: 0.068uF  [1210]  (hidden comment: C1210C683J2RACTU)
C121  VDC_V: 200V  ValueDisplayed: 1µF  [1812_280]  (hidden comment: 18122C105KAT2A)
C122  VDC_V: 200V  ValueDisplayed: 2.2uF  [2220_450]  (hidden comment: 2220Y2000225KXTWS2)
C123  VDC_V: 200V  ValueDisplayed: 2.2uF  [2220_450]  (hidden comment: 2220Y2000225KXTWS2)
C124  VDC_V: 50V  ValueDisplayed: 2200pF  [0402]  (hidden comment: GCM155R71H222KA37D)
C125  VDC_V: 50V  ValueDisplayed: 2200pF  [0402]  (hidden comment: GCM155R71H222KA37D)
C126  Cap_F: 22µF  VDC_V: 10V  [0805_HV]  (hidden comment: GRM21BZ71A226ME15L)
C127  Cap_F: 22µF  VDC_V: 10V  [0805_HV]  (hidden comment: GRM21BZ71A226ME15L)
C128  VDC_V: 200V  Cap_F: 100nF  [FP-CGA5H2X8R2A104K115AA_1206-MFG]  (hidden comment: C1206C104K2RAC7800)
C129  VDC_V: 160V  ValueDisplayed: 10uF  [FP-EEV-EB2C100Q_RADIAL-MFG]  (hidden comment: EEV-EB2C100Q)
C130  Cap_F: 1µF  VDC_V: 16V  [0603]  (hidden comment: GCM188R71C105KA64D)
C131  ValueDisplayed: NC  [0603]  (hidden comment: GRM1885C1H560JA01D)  (no BOM)
C132  Cap_F: 4.7µF  VDC_V: 16V  [0805_HV]  (hidden comment: GRM21BR71C475KA73L)
C133  Cap_F: 4.7µF  VDC_V: 16V  [0805_HV]  (hidden comment: GRM21BR71C475KA73L)
C134  Cap_F: 4.7µF  VDC_V: 16V  [0805_HV]  (hidden comment: GRM21BR71C475KA73L)
C135  VDC_V: 16V  Cap_F: 2.2µF  [0603]  (hidden comment: GRM188Z71C225KE43)
C136  VDC_V: 16V  Cap_F: 2.2µF  [0603]  (hidden comment: GRM188Z71C225KE43)
D38  SMBJ5376B-TP  value 91V  [SMB]
D39  BAS516,115  [SOD-523]
J6  TSW-102-08-G-S  [Samtec_TSW-102-08-x-S]
J7  TSW-102-08-G-S  [Samtec_TSW-102-08-x-S]
J8  PBC04SAAN  [Sullins_xxC04SAAN]
L1  ValueDisplayed: 1uH  [WE-MAPI_3015]  (hidden comment: 74438335010)
L10  ValueDisplayed: 68uH  [WE-PD_7345]  (hidden comment: 744777168)
L14  74479275222  [WE-PMCI_0805_L2W1.25H1]  (value not drawn)
L15  74479275222  [WE-PMCI_0805_L2W1.25H1]  (value not drawn)
Q67  ZXTN4004KTC  [DPAK]
R1  ValueDisplayed: NC  [0603]  (hidden comment: RC0603JR-070RL)  (no BOM)
R48  ValueDisplayed: NC  [0603]  (hidden comment: RC0603JR-070RL)  (no BOM)
R49  ValueDisplayed: NC  [0603]  (hidden comment: RC0603JR-070RL)  (no BOM)
R187  ValueDisplayed: NC  [0603]  (hidden comment: CRCW04020000Z0ED)  (no BOM)
R200  ValueDisplayed: 100  [0603]  (hidden comment: CRCW0603100RFKEA)
R263  ValueDisplayed: 0  [0603]  (hidden comment: CRCW04020000Z0ED)
R264  ValueDisplayed: 0  [0603]  (hidden comment: CRCW04020000Z0ED)
R265  ValueDisplayed: 0  [0603]  (hidden comment: CRCW04020000Z0ED)
R266  ValueDisplayed: 0  [0603]  (hidden comment: CRCW04020000Z0ED)
R267  ValueDisplayed: 0  [0603]  (hidden comment: CRCW04020000Z0ED)
R308  ValueDisplayed: 200  [2512]  (hidden comment: CRM2512-FX-2000ELF)
R309  ValueDisplayed: 20.0k  [1206]  (hidden comment: RC1206FR-0720KL)
R310  ValueDisplayed: 18.2k  [0603]  (hidden comment: CRCW060318K2FKEA)
R311  ValueDisplayed: 18.2k  [0603]  (hidden comment: CRCW060318K2FKEA)
R317  ValueDisplayed: NC  [0603]  (hidden comment: RC0603FR-07499KL)  (no BOM)
R320  ValueDisplayed: 523k  [0402]  (hidden comment: CRCW0402523KFKED)
R324  ValueDisplayed: 200k  [0603]  (hidden comment: CRCW0603200KFKEA)
R325  ValueDisplayed: 82.5k  [0603]  (hidden comment: CRCW060382K5FKEA)
R328  ValueDisplayed: 63.4k  [0603]  (hidden comment: CRCW060363K4FKEA)
U22  UCC33410  [RAQ0012B-MFG]
U23  PartNumber: UCC33421  [DWX0016A-MFG]  (hidden comment: UCC33421-Q1)
U24  LM5168PDDAR  [DDA0008E_M]
U25  TPS7A2433DBVR  [DBV0005A-MFG]
U26  TPS7A2433DBVR  [DBV0005A-MFG]

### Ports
BAT_IN (in), BOTREG1 (in), PWR_EN (in), UCC_EN1 (in), UCC_EN2 (in)

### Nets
3V3: C136.1 R49.1 U25.5(OUT)
3V3_ISO: R1.1 R266.2
3V3_TOP_ISO: R48.1 R267.2
5V_ISO: C130.1 R187.2 R265.2 U26.1(IN) U26.3(EN)
GND: C114.2 C115.2 C116.2 C117.2 C118.2 C119.2 C120.2 C121.2 C122.2 C123.2 C128.2 C129.1(CATHODE) C131.2 C132.2 C133.2 C134.2 C136.2 D38.2(A) J6.2 R325.1 R328.1 U22.3(GNDP) U22.4(GNDP) U22.5(GNDP) U22.6(GNDP) U23.4(GNDP) U23.5(GNDP) U23.6(GNDP) U23.7(GNDP) U23.8(GNDP) U24.1(GND) U24.9(PAD) U25.2(GND)
GND_SYS: C125.2 C127.2 C130.2 C135.2 J8.2 J8.4 U23.12(GNDS) U23.13(GNDS) U23.14(GNDS) U23.15(GNDS) U23.16(GNDS) U26.2(GND)
UP_GND: C124.2 C126.2 J7.2 U22.9(GNDS) U22.10(GNDS) U22.11(GNDS) U22.12(GNDS)
5V: C114.1 L14.1 L15.1 R264.2 U25.1(IN) U25.3(EN) ; port BOTREG1
BAT_IN: C116.1 R308.1 ; port BAT_IN
EN: U24.3(EN/UVLO) ; port PWR_EN
UCC_EN1: R310.1 ; port UCC_EN1
UCC_EN2: R311.1 ; port UCC_EN2
NetC13_1: C13.1 R263.2
NetC13_2: C13.2 L10.1 R317.2 R320.1 U24.8(SW)
NetC27_1: C27.1 C132.1 C133.1 C134.1 L10.2 R264.1 R324.2
NetC27_2: C27.2 C112.1 R320.2
NetC112_2: C112.2 R324.1 R328.2 U24.5(FB)
NetC115_1: C115.1 C118.1 L14.2 U23.2(VINP) U23.3(VINP)
NetC117_1: C117.1 C119.1 L15.2 U22.2(VINP)
NetC120_1: C120.1 D38.1(K) Q67.1(B) R309.2
NetC121_1: C121.1 D39.2(A) Q67.3(E)
NetC122_1: C122.1 D39.1(K) L1.1
NetC123_1: C123.1 L1.2 R200.1
NetC124_1: C124.1 C126.1 R267.1 U22.7(SEL) U22.8(VCC)
NetC125_1: C125.1 C127.1 R265.1 U23.9(SEL) U23.10(VCC) U23.11(VCC)
NetC128_1: C128.1 C129.2(ANODE) R200.2 U24.2(VIN)
NetC131_1: C131.1 R317.1
NetC135_1: C135.1 R266.1 U26.5(OUT)
NetJ6_1: J6.1 R49.2
NetJ7_1: J7.1 R48.2
NetJ8_1: J8.1 R187.1
NetJ8_3: J8.3 R1.2
NetQ67_4: Q67.4(C) R308.2 R309.1
NetR263_1: R263.1 U24.7(BST)
NetR310_2: R310.2 U23.1(EN/FLT)
NetR311_2: R311.2 U22.1(EN/FLT)
NetR325_2: R325.2 U24.4(RON)

Not connected (* = marked no-connect by the designer): U24 6(PGOOD); U25 4(NC)*; U26 4(NC)*

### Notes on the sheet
- In OTP process, applying 3.3v from external will make the LDO input voltage to 3.1v due to internal body diode conduction. this 3.1v voltage will make ucc334xx working, then the 3.3v_top_iso will be built up which will power up the I2C isolator iso1640. User should make sure cell17-32 are disconnected when OTP the bottom AFE.

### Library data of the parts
C13 = CMP-0006683-1: CAP, CERM, 2200 pF, 50 V, +/- 10%, X7R, 0402; Manufacturer: MuRata; TaMin_C: -55°C; Polarized: N; SizeAreaWB_mm2: 3; Value1: Unknown; U/M: EA; Value: 2200pF; TaMax_C: 125°C; SizeZ_mm: 0.6; SizeX_mm: 1; SizeY_mm: 0.5; Cap_F: 2.2nF; AEC Category: Q200
C27 = CMP-0006678-2: CAP, CERM, 1500 pF, 50 V, +/- 10%, X7R, 0402; Manufacturer: MuRata; TaMin_C: -55°C; Polarized: N; SizeAreaWB_mm2: 3; Value1: Unknown; U/M: EA; Value: 1500pF; TaMax_C: 125°C; SizeZ_mm: 0.6; SizeX_mm: 1; SizeY_mm: 0.5; Cap_F: 1.5nF; AEC Category: Q200
C112 = CMP-0007237-4: as C137 on sheet High side FETs
C114 C130 = CMP-0007136-1: CAP, CERM, 1 uF, 16 V, +/- 10%, X7R, AEC-Q200 Grade 1, 0603; Manufacturer: MuRata; TaMin_C: -55°C; Polarized: N; SizeAreaWB_mm2: 4.68; Value1: Unknown; U/M: EA; Value: 1uF; TaMax_C: 125°C; SizeZ_mm: 1; SizeX_mm: 1.6; SizeY_mm: 0.8; SizeArea_mm2: 1.28; AEC Qualified: Y; AEC Category: Q200
C115 C124 C125 = CMP-0006357-1: CAP, CERM, 2200 pF, 50 V, +/- 10%, X7R, AEC-Q200 Grade 1, 0402; Manufacturer: MuRata; TaMin_C: -55°C; Polarized: N; SizeAreaWB_mm2: 3; Value1: Unknown; U/M: EA; Value: 2200pF; TaMax_C: 125°C; SizeZ_mm: 0.6; SizeX_mm: 1; SizeY_mm: 0.5; AEC Qualified: Y; Cap_F: 2.2nF; AEC Category: Q200
C116 C121 = CMP-0081058-1: CAP, CERM, 1 µF, 200 V,+/- 10%, X7R, 1812; Manufacturer: AVX; TaMin_C: -55°C; Polarized: N; SizeAreaWB_mm2: 23.1; U/M: EA; Value: 1uF; TaMax_C: 125°C; SizeZ_mm: 2.8; SizeX_mm: 4.5; SizeY_mm: 3.2; SizeArea_mm2: 14.4; AEC Category: Q200
C117 = CMP-0006357-2: CAP, CERM, 2200 pF, 50 V, +/- 10%, X7R, AEC-Q200 Grade 1, 0402; Manufacturer: MuRata; TaMin_C: -55°C; Polarized: N; SizeAreaWB_mm2: 3; Value1: Unknown; U/M: EA; Value: 2200pF; TaMax_C: 125°C; SizeZ_mm: 0.6; SizeX_mm: 1; SizeY_mm: 0.5; AEC Qualified: Y; Cap_F: 2.2nF; AEC Category: Q200
C118 C119 C126 C127 = CMP-0008377-2: CAP, CERM, 22 uF, 10 V, +/- 20%, X7R, 0805; Manufacturer: MuRata; SizeY_mm: 1.25; Cap_Case: 0805; SizeArea_mm2: 2.5; AEC Qualified: N; AEC Category: Q200; ValueDisplayed: 22uF; TaMin_C: -55°C; SizeAreaWB_mm2: 6.75; Value1: Unknown; U/M: EA; Value: 22uF; TaMax_C: 125°C; SizeZ_mm: 1.45; SizeX_mm: 2
C120 = CMP-0009089-1: CAP, CERM, 0.068 uF, 200 V, +/- 5%, X7R, 1210; Manufacturer: Kemet; TaMin_C: -55°C; Polarized: N; SizeAreaWB_mm2: 14.7; Value1: Unknown; U/M: EA; TaMax_C: 125°C; SizeZ_mm: 1.35; SizeX_mm: 3.2; SizeY_mm: 2.5; SizeArea_mm2: 8; Cap_F: 68nF; AEC Category: Q200
C122 C123 = CMP-0064919-1: CAP, CERM, 2.2 uF, 200 V,+/- 10%, X7R, 2220; Manufacturer: Knowles Capacitors; PartNumber: 2220Y6300105KXTWS2; TaMin_C: -55°C; Polarized: N; SizeAreaWB_mm2: 53.9; Value1: Unknown; U/M: EA; Value: 1uF; TaMax_C: 125°C; SizeZ_mm: 4.5; SizeX_mm: 5.7; SizeY_mm: 5; Cap_Case: 2220; Value2: 630V; SizeArea_mm2: 28.5; AEC Qualified: Y; Cap_F: 1µF; AEC Grade: 1; AEC Category: Q200
C128 = CMP-0086499-1: Cap Ceramic 0.1uF 200V X7R 10% SMD 1206; Manufacturer: TDK Corporation; SizeZ_mm: 1.3mm; AEC Qualified: Yes; TempCo: 15%; AEC Grade: Grade 0
C129 = CMP-0093400-1: 10 µF 160 V Aluminum Electrolytic Capacitors Radial, Can - SMD - 3000 Hrs @ 105°C; Manufacturer: Panasonic Electronic Components; SizeZ_mm: 14mm; Leakage Current: 106uA; Value: 10µF; Dissipation Factor: 15%; AEC Qualified: No; IRMS_A: 70mA; Life: 3000Hours; Tolerance_%: 20%
C131 = CMP-0007224-1: CAP, CERM, 56 pF, 50 V, +/- 5%, C0G/NP0, 0603; Manufacturer: MuRata; TaMin_C: -55°C; Polarized: N; SizeAreaWB_mm2: 4.68; Value1: Unknown; U/M: EA; Value: 56pF; TaMax_C: 125°C; SizeZ_mm: 1; SizeX_mm: 1.6; SizeY_mm: 0.8; Value2: 50V; SizeArea_mm2: 1.28; AEC Category: Q200
C132-C134 = CMP-0008334-1: CAP, CERM, 4.7 uF, 16 V, +/- 10%, X7R, 0805; Manufacturer: MuRata; TaMin_C: -55°C; ESR_ohm: 6m; Polarized: N; SizeAreaWB_mm2: 6.75; Value1: 0.006 ohm; U/M: EA; Value: 4.7uF; TaMax_C: 125°C; SizeZ_mm: 1.45; SizeX_mm: 2; SizeY_mm: 1.25; Cap_Case: 0805; SizeArea_mm2: 2.5; AEC Category: Q200
C135 C136 = CMP-0007499-1: CAP, CERM, 2.2 uF, 16 V, +/- 10%, X7R, 0603; Manufacturer: MuRata; TaMin_C: -55°C; Polarized: N; SizeAreaWB_mm2: 4.68; Value1: Unknown; U/M: EA; Value: 2.2uF; TaMax_C: 125°C; SizeZ_mm: 1; SizeX_mm: 1.6; SizeY_mm: 0.8; SizeArea_mm2: 1.28; AEC Category: Q200
D38 = CMP-0005625-1: Diode, Zener, 91 V, 5 W, SMB; Manufacturer: Micro Commercial Components; PartNumber: SMBJ5375B-TP; Power_W: 5W; SizeAreaWB_mm2: 44.156; Vz_V: 82V; RJA_CperW: 90; U/M: EA; SizeZ_mm: 2.6; SizeX_mm: 5.6; SizeY_mm: 3.81; SizeArea_mm2: 21.336; AEC Qualified: N; AEC Category: Q101
D39 = CMP-0076979-3: Diode, Switching, 100 V, 0.25 A, SOD-523; Manufacturer: Nexperia; Value: 100V; SizeAreaWB_mm2: 5.13; Vf_V: 1.25V; SizeArea_mm2: 1.53; SizeY_mm: 0.9; Green_Lifecycle: Not Set; AEC Category: Q101; SizeX_mm: 1.7; Green_REACh: Incomplete; Io_A: 250mA; TJmax_C: 150°C; SizeZ_mm: 0.65; Value1: 0.25A
J6 J7 = CMP-0077643-1: Header, 2.54mm, 2x1, Gold, TH; Manufacturer: Samtec; Pitch_mm: 2.54; Gender: Male; Cert_CSA: Y; Current_A: 5.7A; Voltage_V: 550V; Row_Count: 1
J8 = CMP-0054583-1: Header, 2.54 mm, 4x1, Gold, TH; Manufacturer: Sullins Connector Solutions; CNHeader: TRUE; Current_A: 3A; Green_Lifecycle: Not Set; Shrouded: N; Gender: Male; Green_REACh: Incomplete; Voltage_V: 1.8kV; Row_Count: 1; Pitch_mm: 2.54; CT: FALSE; Cert_UL: Y
L1 = CMP-0064154-1: Inductor, Shielded, 1 uH, 2.7 A, 0.039 ohm, SMD; Manufacturer: Wurth Elektronik; Isat: 4.5A @ 20% inductance drop; Irms: 2.7A @ 40C rise; Green_Lifecycle: Active; SizeAreaWB_mm2: 16; DCR_ohm: 39m; Green_REACh: Passed; Value: 1uH; Imax_A: 2.7A; SizeZ_mm: 1.2; SizeX_mm: 3; SizeArea_mm2: 9; Ind_H: 1µH; AEC Category: Q200
L10 = CMP-0064631-1: Inductor, Shielded Drum Core, Metal Composite, 68 uH, 0.87 A, 0.239 ohm, SMD; Manufacturer: Wurth Elektronik; Isat: 0.95A @ 10% inductance drop; Irms: 0.87A @ 40C rise; Green_Lifecycle: Active; SizeAreaWB_mm2: 86.49; DCR_ohm: 0.239; Green_REACh: Passed; Value: 68uH; Imax_A: 870mA; SizeZ_mm: 4.5; SizeX_mm: 7.3; Value2: 0.87A; SizeArea_mm2: 53.29; Ind_H: 68µH; AEC Category: Q200
L14 L15 = CMP-0100941-1: WE-PMCI SMT Power Molded Chip Inductor, size 0805, 2.2uH, 2.1A, 190mOhm; Manufacturer: Wurth Elektronik; Case/Size Code: 0805; DC Resistance: 180mOhm; Saturation Current: 2.4A; Self Resonant Frequency: 45MHz; Type: Standard
Q67 = CMP-0000504-2: Transistor, NPN, 150 V, 1 A, AEC-Q101, DPAK; Manufacturer: Diodes Inc.; TaMax_C: 150°C; Value1: 1 A; Vcesat1_V: 250mV; SizeX_mm: 9.91; SizeY_mm: 6.54; TaMin_C: -55°C; IcRated_A: 1A; CompType: BJT; SizeZ_mm: 2.29; AEC Qualified: Y; Value: 150 V; SizeArea_mm2: 64.8114; NPN: 1; Vceo_V: 150V; PNP: 0; AEC Category: Q101; SizeAreaWB_mm2: 101.7114; U/M: EA
R1 R48 R49 = CMP-0025885-5: RES, 0, 5%, 0.1 W, 0603; Manufacturer: Yageo; Power_W: 100mW; TempCo: 200 ppm/C; Value_Code: 0000; Value: 0; EIA_Code: E24; SizeX_mm: 1.6; SizeY_mm: 0.8; SizeZ_mm: 1; Value2: 0.1W; SizeArea_mm2: 1.28; AEC Qualified: N; VDC_V: 75V; AEC Category: Q200; SizeAreaWB_mm2: 4.68
R187 R263-R267 = CRCW04020000Z0ED: as R273 on sheet High side FETs
R200 = CMP-0021991-2: as R292 on sheet High side FETs
R308 = CMP-0078952-1: RES, 200, 1%, 2 W, 2512; Manufacturer: Bourns; Value_Code: 200R; SizeArea_mm2: 20.16; AEC Qualified: N; AEC Category: Q200; Value: 200; SizeZ_mm: 0.71; EIA_Code: E96; TempCo: 100 ppm/C; Power_W: 2W; VDC_V: 300V; SizeY_mm: 3.2; SizeX_mm: 6.3
R309 = CMP-0018065-2: RES, 20.0 k, 1%, 0.25 W, 1206; Manufacturer: Yageo America; Power_W: 250mW; TempCo: 100 ppm/C; Value_Code: 20k0; U/M: EA; Value: 20.0k; EIA_Code: E96; Res_ohm: 20k; SizeX_mm: 3.2; SizeY_mm: 1.6; SizeZ_mm: 1.35; Value2: 0.25W; SizeArea_mm2: 5.12; VDC_V: 200V; AEC Category: Q200
R310 R311 = CMP-0022097-1: RES, 18.2 k, 1%, 0.1 W, 0603; Manufacturer: Vishay-Dale; Power_W: 100mW; TempCo: 100 ppm/C; Value_Code: 18k2; U/M: EA; Value: 18.2k; EIA_Code: E96; SizeX_mm: 1.6; SizeY_mm: 0.8; SizeZ_mm: 1; Value2: 0.1W; SizeArea_mm2: 1.28; VDC_V: 75V; AEC Category: Q200
R317 = CMP-0023140-4: RES, 499 k, 1%, 0.1 W, 0603; Manufacturer: Yageo; Power_W: 100mW; TempCo: 100 ppm/C; Value_Code: 499k; Value: 499k; EIA_Code: E96; SizeX_mm: 1.6; SizeY_mm: 0.8; SizeZ_mm: 1; Value2: 0.1W; SizeArea_mm2: 1.28; AEC Qualified: N; VDC_V: 75V; AEC Category: Q200; SizeAreaWB_mm2: 4.68
R320 = CMP-0026439-2: RES, 523 k, 1%, 0.063 W, AEC-Q200 Grade 0, 0402; Manufacturer: Vishay-Dale; Power_W: 63mW; TempCo: 100 ppm/C; Value: 523k; EIA_Code: E96; SizeX_mm: 1; SizeY_mm: 0.5; SizeZ_mm: 0.6; Value2: 0.063W; AEC Qualified: Y; VDC_V: 50V; AEC Category: Q200; AEC Grade: 0
R324 = CMP-0022200-2: RES, 200 k, 1%, 0.1 W, 0603; Manufacturer: Vishay-Dale; Power_W: 100mW; TempCo: 100 ppm/C; U/M: EA; Value: 200k; EIA_Code: E96; SizeX_mm: 1.6; SizeY_mm: 0.8; SizeZ_mm: 1; Value2: 0.1W; SizeArea_mm2: 1.28; VDC_V: 75V; AEC Category: Q200
R325 = CMP-0022620-1: RES, 82.5 k, 1%, 0.1 W, 0603; Manufacturer: Vishay-Dale; Power_W: 100mW; TempCo: 100 ppm/C; Value_Code: 82k5; U/M: EA; Value: 82.5k; EIA_Code: E96; SizeX_mm: 1.6; SizeY_mm: 0.8; SizeZ_mm: 1; Value2: 0.1W; SizeArea_mm2: 1.28; VDC_V: 75V; AEC Category: Q200
R328 = CMP-0022540-4: RES, 63.4 k, 1%, 0.1 W, AEC-Q200 Grade 0, 0603; Manufacturer: Vishay-Dale; Power_W: 100mW; TempCo: 100 ppm/C; Value_Code: 63k4; Value: 63.4k; EIA_Code: E96; SizeX_mm: 1.6; SizeY_mm: 0.8; SizeZ_mm: 1; Value2: 0.1W; SizeArea_mm2: 1.28; AEC Qualified: Y; VDC_V: 75V; AEC Category: Q200; AEC Grade: 0
U22 = CMP-0098322-4: 1.5W, High-Density, >3 kVRMS Isolated DC-DC Converter; Manufacturer: Texas Instruments; Part Number: UCC33420; SizeZ_mm: 1.05mm; AEC Qualified: No; AEC Grade: NA; Max Supply Voltage: 5.5V; Min Supply Voltage: 4.5V; Number Of Outputs: 1; Output Type: Fixed; Output Voltage: 5V; AEC Category: Q200; CompType: IC
U23 = CMP-0120108-2: 1.5W, High-Density, >5 kVRMS Isolated DC-DC Converter; Manufacturer: Texas Instruments; SizeZ_mm: 2.6mm; AEC Qualified: No; Max Supply Voltage: 5.5V; Min Supply Voltage: 4.5V; Number Of Outputs: 1; Output Type: AdjustableProgrammable; Output Voltage: 5/5.5V; Standoff Height: 0.14mm; AEC Category: Q200; CompType: IC
U24 = CMP-0861029-1: 0.3-A,120-V, Step-Down Converter with Fly-buck Capability; Alternate Manufacturer: Texas Instruments; SizeAreaWB_mm2: 55.2; SizeZ_mm: 1.7; SizeX_mm: 6; AEC Qualified: N; AEC Category: Q200; SizeArea_mm2: 29.4; CompType: IC; SizeY_mm: 4.9
U25 U26 = CMP-0120272-1: 200-mA, 18-V, ultra-low-IQ, low-dropout (LDO) voltage regulator with enable 5-SOT-23 -40 to 125; Manufacturer: Texas Instruments; SizeZ_mm: 1.45mm; AEC Qualified: No; Accuracy Percentage: 1.25%; Dropout Voltage: 160mV; Max Supply Voltage: 18V; Min Supply Voltage: 3.8V; Nominal Supply Current: 2-15uA; Number Of Outputs: 1; Output Type: Fixed; Output Voltage: 3.3V; Standoff Height: 0mm; TJmax_C: +125°C

## Sheet Temp Sensing.SchDoc
size A3; SheetNumber: 6; SheetTotal: 10
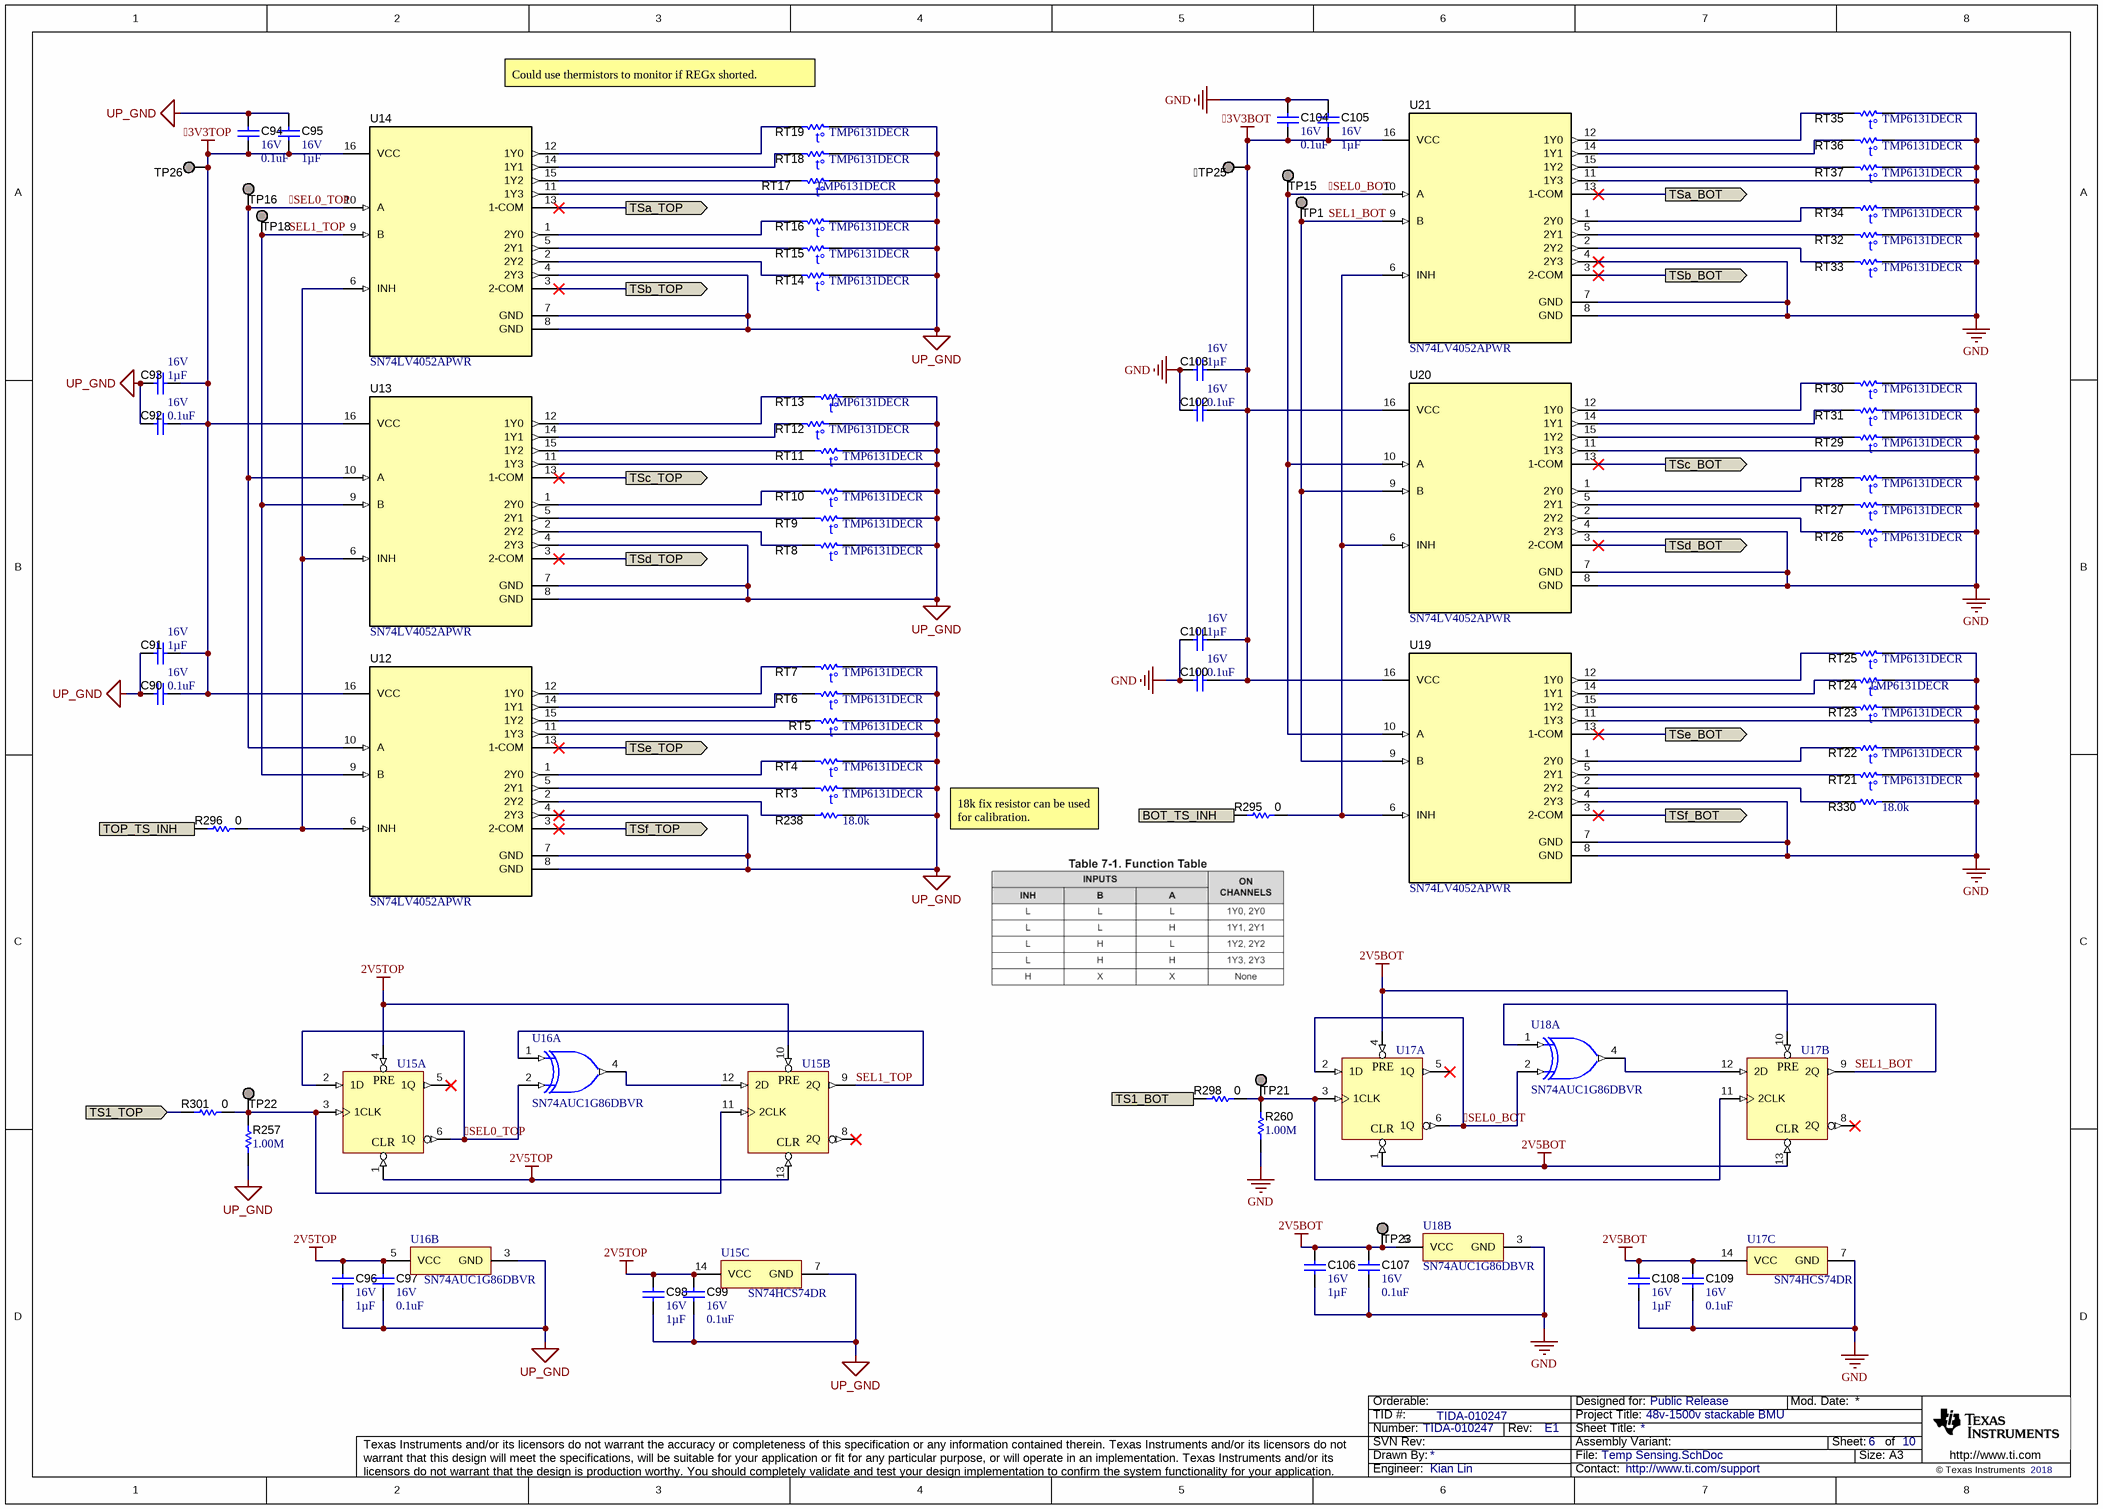
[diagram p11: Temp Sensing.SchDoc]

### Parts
TP25    [TP_SM_1MM]  (value not drawn)  (no BOM)
C90  VDC_V: 16V  ValueDisplayed: 0.1uF  [0603]  (hidden comment: GRM188R61C104KA01D)
C91  VDC_V: 16V  ValueDisplayed: 1µF  [0603]  (hidden comment: CC0603MRX5R7BB105)
C92  VDC_V: 16V  ValueDisplayed: 0.1uF  [0603]  (hidden comment: GRM188R61C104KA01D)
C93  VDC_V: 16V  ValueDisplayed: 1µF  [0603]  (hidden comment: CC0603MRX5R7BB105)
C94  VDC_V: 16V  ValueDisplayed: 0.1uF  [0603]  (hidden comment: GRM188R61C104KA01D)
C95  VDC_V: 16V  ValueDisplayed: 1µF  [0603]  (hidden comment: CC0603MRX5R7BB105)
C96  VDC_V: 16V  ValueDisplayed: 1µF  [0603]  (hidden comment: CC0603MRX5R7BB105)
C97  VDC_V: 16V  ValueDisplayed: 0.1uF  [0603]  (hidden comment: GRM188R61C104KA01D)
C98  VDC_V: 16V  ValueDisplayed: 1µF  [0603]  (hidden comment: CC0603MRX5R7BB105)
C99  VDC_V: 16V  ValueDisplayed: 0.1uF  [0603]  (hidden comment: GRM188R61C104KA01D)
C100  VDC_V: 16V  ValueDisplayed: 0.1uF  [0603]  (hidden comment: GRM188R61C104KA01D)
C101  VDC_V: 16V  ValueDisplayed: 1µF  [0603]  (hidden comment: CC0603MRX5R7BB105)
C102  VDC_V: 16V  ValueDisplayed: 0.1uF  [0603]  (hidden comment: GRM188R61C104KA01D)
C103  VDC_V: 16V  ValueDisplayed: 1µF  [0603]  (hidden comment: CC0603MRX5R7BB105)
C104  VDC_V: 16V  ValueDisplayed: 0.1uF  [0603]  (hidden comment: GRM188R61C104KA01D)
C105  VDC_V: 16V  ValueDisplayed: 1µF  [0603]  (hidden comment: CC0603MRX5R7BB105)
C106  VDC_V: 16V  ValueDisplayed: 1µF  [0603]  (hidden comment: CC0603MRX5R7BB105)
C107  VDC_V: 16V  ValueDisplayed: 0.1uF  [0603]  (hidden comment: GRM188R61C104KA01D)
C108  VDC_V: 16V  ValueDisplayed: 1µF  [0603]  (hidden comment: CC0603MRX5R7BB105)
C109  VDC_V: 16V  ValueDisplayed: 0.1uF  [0603]  (hidden comment: GRM188R61C104KA01D)
R238  ValueDisplayed: 18.0k  [0603]  (hidden comment: RT0603BRD0718KL)
R257  ValueDisplayed: 1.00M  [0603]  (hidden comment: MCT06030C1004FP500)
R260  ValueDisplayed: 1.00M  [0603]  (hidden comment: MCT06030C1004FP500)
R295  ValueDisplayed: 0  [0603]  (hidden comment: CRCW04020000Z0ED)
R296  ValueDisplayed: 0  [0603]  (hidden comment: CRCW04020000Z0ED)
R298  ValueDisplayed: 0  [0603]  (hidden comment: CRCW04020000Z0ED)
R301  ValueDisplayed: 0  [0603]  (hidden comment: CRCW04020000Z0ED)
R330  ValueDisplayed: 18.0k  [0603]  (hidden comment: RT0603BRD0718KL)
RT3  TMP6131DECR  [DEC0002A]
RT4  TMP6131DECR  [DEC0002A]
RT5  TMP6131DECR  [DEC0002A]
RT6  TMP6131DECR  [DEC0002A]
RT7  TMP6131DECR  [DEC0002A]
RT8  TMP6131DECR  [DEC0002A]
RT9  TMP6131DECR  [DEC0002A]
RT10  TMP6131DECR  [DEC0002A]
RT11  TMP6131DECR  [DEC0002A]
RT12  TMP6131DECR  [DEC0002A]
RT13  TMP6131DECR  [DEC0002A]
RT14  TMP6131DECR  [DEC0002A]
RT15  TMP6131DECR  [DEC0002A]
RT16  TMP6131DECR  [DEC0002A]
RT17  TMP6131DECR  [DEC0002A]
RT18  TMP6131DECR  [DEC0002A]
RT19  TMP6131DECR  [DEC0002A]
RT21  TMP6131DECR  [DEC0002A]
RT22  TMP6131DECR  [DEC0002A]
RT23  TMP6131DECR  [DEC0002A]
RT24  TMP6131DECR  [DEC0002A]
RT25  TMP6131DECR  [DEC0002A]
RT26  TMP6131DECR  [DEC0002A]
RT27  TMP6131DECR  [DEC0002A]
RT28  TMP6131DECR  [DEC0002A]
RT29  TMP6131DECR  [DEC0002A]
RT30  TMP6131DECR  [DEC0002A]
RT31  TMP6131DECR  [DEC0002A]
RT32  TMP6131DECR  [DEC0002A]
RT33  TMP6131DECR  [DEC0002A]
RT34  TMP6131DECR  [DEC0002A]
RT35  TMP6131DECR  [DEC0002A]
RT36  TMP6131DECR  [DEC0002A]
RT37  TMP6131DECR  [DEC0002A]
TP1    [TP_SM_1MM]  (value not drawn)  (no BOM)
TP15    [TP_SM_1MM]  (value not drawn)  (no BOM)
TP16    [TP_SM_1MM]  (value not drawn)  (no BOM)
TP18    [TP_SM_1MM]  (value not drawn)  (no BOM)
TP21    [TP_SM_1MM]  (value not drawn)  (no BOM)
TP22    [TP_SM_1MM]  (value not drawn)  (no BOM)
TP23    [TP_SM_1MM]  (value not drawn)  (no BOM)
TP26    [TP_SM_1MM]  (value not drawn)  (no BOM)
U12  SN74LV4052APWR  [PW0016A_N]
U13  SN74LV4052APWR  [PW0016A_N]
U14  SN74LV4052APWR  [PW0016A_N]
U15  SN74HCS74DR  [D0014A_N]  (value not drawn)  (parts A,B,C of 3)
U16  SN74AUC1G86DBVR  [DBV0005A_N]  (parts A,B of 2)
U17  SN74HCS74DR  [D0014A_N]  (value not drawn)  (parts A,B,C of 3)
U18  SN74AUC1G86DBVR  [DBV0005A_N]  (parts A,B of 2)
U19  SN74LV4052APWR  [PW0016A_N]
U20  SN74LV4052APWR  [PW0016A_N]
U21  SN74LV4052APWR  [PW0016A_N]

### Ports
BOT_TS_INH (in), TOP_TS_INH (in), TS1_BOT (in), TS1_TOP (in), TSa_BOT (out), TSa_TOP (out), TSb_BOT (out), TSb_TOP (out), TSc_BOT (out), TSc_TOP (out), TSd_BOT (out), TSd_TOP (out), TSe_BOT (out), TSe_TOP (out), TSf_BOT (out), TSf_TOP (out)

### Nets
2V5BOT: C106.1 C107.1 C108.1 C109.1 TP23.1 U17.1(1~{CLR}) U17.4(1~{PRE}) U17.10(2~{PRE}) U17.13(2~{CLR}) U17.14(VCC) U18.5(VCC)
2V5TOP: C96.1 C97.1 C98.1 C99.1 U15.1(1~{CLR}) U15.4(1~{PRE}) U15.10(2~{PRE}) U15.13(2~{CLR}) U15.14(VCC) U16.5(VCC)
3V3BOT: TP25.1 C100.1 C101.1 C102.1 C103.1 C104.1 C105.1 U19.16(VCC) U20.16(VCC) U21.16(VCC)
3V3TOP: C90.1 C91.1 C92.1 C93.1 C94.1 C95.1 TP26.1 U12.16(VCC) U13.16(VCC) U14.16(VCC)
GND: C100.2 C101.2 C102.2 C103.2 C104.2 C105.2 C106.2 C107.2 C108.2 C109.2 R260.1 R330.2 RT21.1 RT22.1 RT23.1 RT24.1 RT25.1 RT26.1 RT27.1 RT28.1 RT29.1 RT30.1 RT31.1 RT32.1 RT33.1 RT34.1 RT35.1 RT36.1 RT37.1 U17.7(GND) U18.3(GND) U19.4(2Y3) U19.7(GND) U19.8(GND) U19.11(1Y3) U20.4(2Y3) U20.7(GND) U20.8(GND) U20.11(1Y3) U21.4(2Y3) U21.7(GND) U21.8(GND) U21.11(1Y3)
UP_GND: C90.2 C91.2 C92.2 C93.2 C94.2 C95.2 C96.2 C97.2 C98.2 C99.2 R238.2 R257.1 RT3.1 RT4.1 RT5.1 RT6.1 RT7.1 RT8.1 RT9.1 RT10.1 RT11.1 RT12.1 RT13.1 RT14.1 RT15.1 RT16.1 RT17.1 RT18.1 RT19.1 U12.4(2Y3) U12.7(GND) U12.8(GND) U12.11(1Y3) U13.4(2Y3) U13.7(GND) U13.8(GND) U13.11(1Y3) U14.4(2Y3) U14.7(GND) U14.8(GND) U14.11(1Y3) U15.7(GND) U16.3(GND)
SEL0_BOT: TP15.1 U17.2(1D) U17.6(1Q) U18.2(B) U19.10(A) U20.10(A) U21.10(A)
SEL0_TOP: TP16.1 U12.10(A) U13.10(A) U14.10(A) U15.2(1D) U15.6(1Q) U16.2(B)
BOT_INH: R295.1 ; port BOT_TS_INH
SEL1_BOT: TP1.1 U17.9(2Q) U18.1(A) U19.9(B) U20.9(B) U21.9(B)
SEL1_TOP: TP18.1 U12.9(B) U13.9(B) U14.9(B) U15.9(2Q) U16.1(A)
TOP_TS_INH: R296.1 ; port TOP_TS_INH
TS1_BOT: R298.1 ; port TS1_BOT
TS1_TOP: R301.1 ; port TS1_TOP
TSa_BOT: U21.13(1-COM) ; port TSa_BOT
TSa_TOP: U14.13(1-COM) ; port TSa_TOP
TSb_BOT: U21.3(2-COM) ; port TSb_BOT
TSb_TOP: U14.3(2-COM) ; port TSb_TOP
TSc_BOT: U20.13(1-COM) ; port TSc_BOT
TSc_TOP: U13.13(1-COM) ; port TSc_TOP
TSd_BOT: U20.3(2-COM) ; port TSd_BOT
TSd_TOP: U13.3(2-COM) ; port TSd_TOP
TSe_BOT: U19.13(1-COM) ; port TSe_BOT
TSe_TOP: U12.13(1-COM) ; port TSe_TOP
TSf_BOT: U19.3(2-COM) ; port TSf_BOT
TSf_TOP: U12.3(2-COM) ; port TSf_TOP
NetR238_1: R238.1 U12.2(2Y2)
NetR257_2: R257.2 R301.2 TP22.1 U15.3(1CLK) U15.11(2CLK)
NetR260_2: R260.2 R298.2 TP21.1 U17.3(1CLK) U17.11(2CLK)
NetR295_2: R295.2 U19.6(INH) U20.6(INH) U21.6(INH)
NetR296_2: R296.2 U12.6(INH) U13.6(INH) U14.6(INH)
NetR330_1: R330.1 U19.2(2Y2)
NetRT3_2: RT3.2 U12.5(2Y1)
NetRT4_2: RT4.2 U12.1(2Y0)
NetRT5_2: RT5.2 U12.15(1Y2)
NetRT6_2: RT6.2 U12.14(1Y1)
NetRT7_2: RT7.2 U12.12(1Y0)
NetRT8_2: RT8.2 U13.2(2Y2)
NetRT9_2: RT9.2 U13.5(2Y1)
NetRT10_2: RT10.2 U13.1(2Y0)
NetRT11_2: RT11.2 U13.15(1Y2)
NetRT12_2: RT12.2 U13.14(1Y1)
NetRT13_2: RT13.2 U13.12(1Y0)
NetRT14_2: RT14.2 U14.2(2Y2)
NetRT15_2: RT15.2 U14.5(2Y1)
NetRT16_2: RT16.2 U14.1(2Y0)
NetRT17_2: RT17.2 U14.15(1Y2)
NetRT18_2: RT18.2 U14.14(1Y1)
NetRT19_2: RT19.2 U14.12(1Y0)
NetRT21_2: RT21.2 U19.5(2Y1)
NetRT22_2: RT22.2 U19.1(2Y0)
NetRT23_2: RT23.2 U19.15(1Y2)
NetRT24_2: RT24.2 U19.14(1Y1)
NetRT25_2: RT25.2 U19.12(1Y0)
NetRT26_2: RT26.2 U20.2(2Y2)
NetRT27_2: RT27.2 U20.5(2Y1)
NetRT28_2: RT28.2 U20.1(2Y0)
NetRT29_2: RT29.2 U20.15(1Y2)
NetRT30_2: RT30.2 U20.12(1Y0)
NetRT31_2: RT31.2 U20.14(1Y1)
NetRT32_2: RT32.2 U21.5(2Y1)
NetRT33_2: RT33.2 U21.2(2Y2)
NetRT34_2: RT34.2 U21.1(2Y0)
NetRT35_2: RT35.2 U21.12(1Y0)
NetRT36_2: RT36.2 U21.14(1Y1)
NetRT37_2: RT37.2 U21.15(1Y2)
NetU15_12: U15.12(2D) U16.4(Y)
NetU17_12: U17.12(2D) U18.4(Y)

Not connected (* = marked no-connect by the designer): U15 5(1Q)* 8(2Q)*; U17 5(1Q)* 8(2Q)*

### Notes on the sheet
- (near RT19) Could use thermistors to monitor if REGx shorted.
- 18k fix resistor can be used for calibration.

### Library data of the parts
TP25 TP1 TP15 TP16 TP18 TP21-TP23 TP26 = CMP-0003825-1: 1mm Test Point, SMT; Manufacturer: Any
C90 C92 C94 C97 C99 C100 C102 C104 C107 C109 = CMP-0007334-3: CAP, CERM, 0.1 uF, 16 V, +/- 10%, X5R, 0603; Manufacturer: MuRata; TaMin_C: -55°C; Polarized: N; SizeAreaWB_mm2: 4.68; Value1: Unknown; U/M: EA; Value: 0.1uF; TaMax_C: 85°C; SizeZ_mm: 1; SizeX_mm: 1.6; SizeY_mm: 0.8; SizeArea_mm2: 1.28; Cap_F: 100nF; AEC Category: Q200
C91 C93 C95 C96 C98 C101 C103 C105 C106 C108 = CMP-0081458-1: CAP, CERM, 1 µF, 16 V,+/- 20%, X5R, 0603; Manufacturer: Yageo America; TaMin_C: -55°C; Polarized: N; SizeAreaWB_mm2: 4.68; U/M: EA; Value: 1uF; TaMax_C: 85°C; SizeZ_mm: 1; SizeX_mm: 1.6; SizeY_mm: 0.8; SizeArea_mm2: 1.28; AEC Category: Q200
R238 R330 = CMP-0023840-3: RES, 18.0 k, 0.1%, 0.1 W, 0603; Manufacturer: Yageo America; Power_W: 100mW; TempCo: 25 ppm/C; Value_Code: 18k0; U/M: EA; Value: 18.0k; EIA_Code: E192; Res_ohm: 18k; SizeX_mm: 1.6; SizeY_mm: 0.8; SizeZ_mm: 1; Value2: 0.1W; SizeArea_mm2: 1.28; VDC_V: 75V; AEC Category: Q200
R257 R260 = CMP-0022731-2: RES, 1.00 M, 1%, 0.125 W, 0603; Manufacturer: Vishay/Beyschlag; Power_W: 125mW; TempCo: 50 ppm/C; Value_Code: 1M00; U/M: EA; Value: 1.00Meg; EIA_Code: E96; Res_ohm: 1M; SizeX_mm: 1.6; SizeY_mm: 0.8; SizeZ_mm: 1; Value2: 0.125W; SizeArea_mm2: 1.28; AEC Qualified: N; VDC_V: 75V; AEC Category: Q200
R295 R296 R298 R301 = CRCW04020000Z0ED: as R273 on sheet High side FETs
RT3-RT19 RT21-RT37 = CMP-0084566-1: Thermistor, DEC0002A (X1SON-2); Alternate Manufacturer: Texas Instruments; Alternate PartNumber: TMP6131DECT; CompType: IC; AEC Category: Q200; SizeX_mm: 1; AEC Qualified: N; SizeZ_mm: 0.5; SizeArea_mm2: 0.6; SizeAreaWB_mm2: 3.2
U12-U14 U19-U21 = CMP-0066257-1: Catalog Dual 4-Channel Analog Multiplexer/Demultiplexer, PW0016A (TSSOP-16); Alternate Manufacturer: Texas Instruments; SizeAreaWB_mm2: 58.8; U/M: EA; SizeZ_mm: 1.2; SizeX_mm: 6.4; SizeY_mm: 5.0; SizeArea_mm2: 32.0; CompType: IC
U15 U17 = CMP-0049499-1: Schmitt-trigger input dual D-type positive-edge-triggered flip-flops w/ clear and preset; Manufacturer: Texas Instruments; Output Drive (IOL/IOH)(Max)(mA): 24/-24; ICC @ Nom Voltage(Max)(mA): 0.01; Rating: Catalog; VCC(Min)(V): 1.65; Schmitt Trigger: Yes; Input Type: CMOS; Output Logic: Inverted,Non-inverted; Technology Family: LVC; Bits(#): 2; Voltage(Nom)(V): 1.8,2.5,2.7,3.3; tpd @ Nom Voltage(Max)(ns): 7.1,4.4,6,5.2; F @ Nom Voltage(Max)(Mhz): 100; VCC(Max)(V): 3.6; 3-State Output: No
U16 U18 = CMP-0052043-2: Single 2-Input Exclusive-OR Gate, DBV0005A (SOT-23-5); Manufacturer: Texas Instruments; Output Drive (IOL/IOH)(Max)(mA): 9/-9; VCC(Max)(V): 2.7; 3-State Output: No; Input Type: CMOS; Gate Type: XOR; Logic: True; VCC(Min)(V): 0.8; F @ Nom Voltage(Max)(Mhz): 250; tpd @ Nom Voltage(Max)(ns): 5.5,3.8,2.6,1.7,1.3; Voltage(Nom)(V): 0.8,1.2,1.5,1.8,2.5; Rating: Catalog; Bits(#): 1; ICC @ Nom Voltage(Max)(mA): 0.01; AEC Category: Q200; AEC Qualified: N; CompType: IC; SizeAreaWB_mm2: 14.82; SizeArea_mm2: 8.12; SizeX_mm: 2.8; SizeY_mm: 2.9; SizeZ_mm: 1.45

## Sheet EVM_Hardware.SchDoc
size 431 x 279 mm; Date: Not shown in title block; ApprovedBy: Not shown in title block; CheckedBy: Not shown in title block; Author: Not shown in title block; CompanyName: Not shown in title block; Engineer: Not shown in title block; Organization: Not shown in title block; Address1: Not shown in title block; Address2: Not shown in title block; Address3: Not shown in title block; Address4: Not shown in title block; DocumentNumber: 7; Revision: Use project parameter SCH_Rev; SheetNumber: 10; SheetTotal: 10; PageSetup: Record=PageOptions¦CenterHorizontal=True¦CenterVertical=True¦PrintScale=1.00¦XCorrection=1.00¦YCorrection=1.00¦PrintKind=0¦BorderSize=5000000¦LeftOffset=0¦BottomOffset=0¦Orientation=2¦PaperLength=1000¦PaperWidth=1000¦Scale=100¦PaperSource=15¦PrintQuality=600¦MediaType=1¦DitherType=10¦PaperKind=Letter¦PrintScaleMode=1
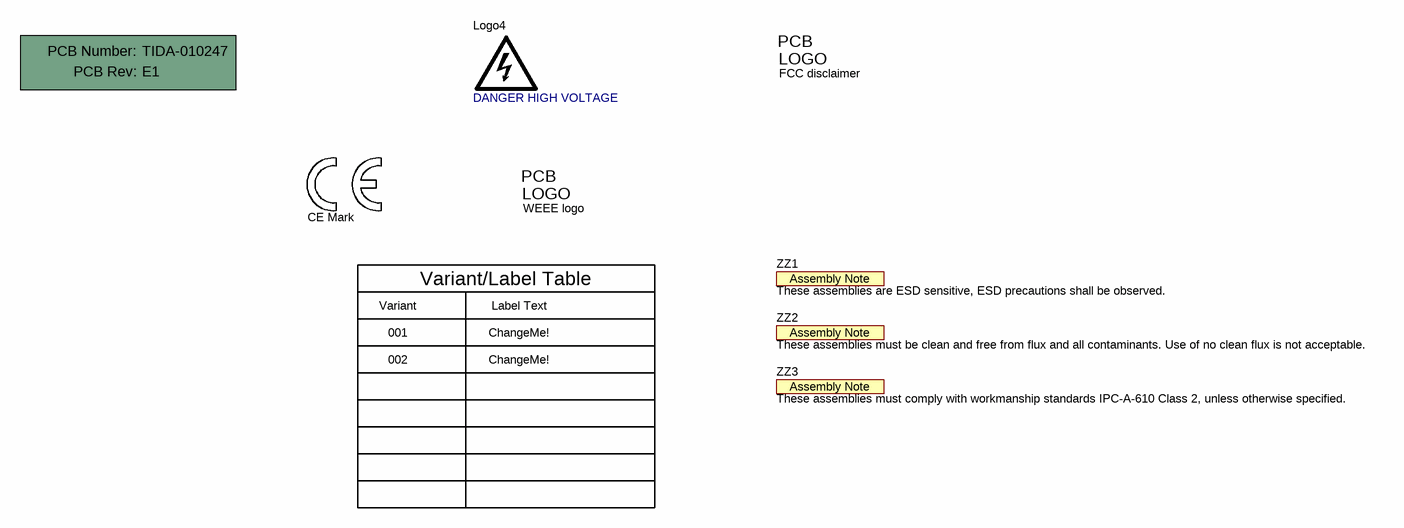
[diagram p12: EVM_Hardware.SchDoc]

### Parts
!PCB1  Printed Circuit Board  (value not drawn)  (mechanical)
Logo3  FCC disclaimer  [FCC_disclaimer]  (no BOM)
Logo4  DANGER HIGH VOLTAGE  [IEC_HighVoltage_Small]  (no BOM)
Logo5  CE Mark  [CE_Mark_5mm]  (no BOM)
Logo6  WEEE logo  [WEEE_Minimum]  (no BOM)
ZZ1  These assemblies are ESD sensitive, ESD precautions shall be observed.  [AssemblyNote]  (no BOM)
ZZ2  These assemblies must be clean and free from flux and all contaminants. Use of no clean flux is not acceptable.  [AssemblyNote]  (no BOM)
ZZ3  These assemblies must comply with workmanship standards IPC-A-610 Class 2, unless otherwise specified.  [AssemblyNote]  (no BOM)

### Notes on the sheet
- Variant
- Variant/Label Table
- Label Text
- 001
- 002
- ChangeMe!

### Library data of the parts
!PCB1 = CMP-0003618-2: Manufacturer: Any; PartNumber: TIDA-010247
Logo3 = CMP-0074847-1: FCC_disclaimer; Library Reference: Logo
Logo4 = CMP-0074835-1: IEC 61010-1 High Voltage Warning; SymbolCreator: a0412235
Logo5 = CMP-0074844-1: SymbolCreator: a0412235
Logo6 = CMP-0074769-1
ZZ1 = CMP-0077236-1
ZZ2 = CMP-0077237-1
ZZ3 = CMP-0077238-1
